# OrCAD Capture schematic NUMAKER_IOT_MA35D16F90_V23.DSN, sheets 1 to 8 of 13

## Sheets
1 00. System Block: size A; title: NuMaker-IoT-MA35D16F90 (LQFP216); rev: V2.3; company: nuvoTon Technology Corp.; note: 00. System Block
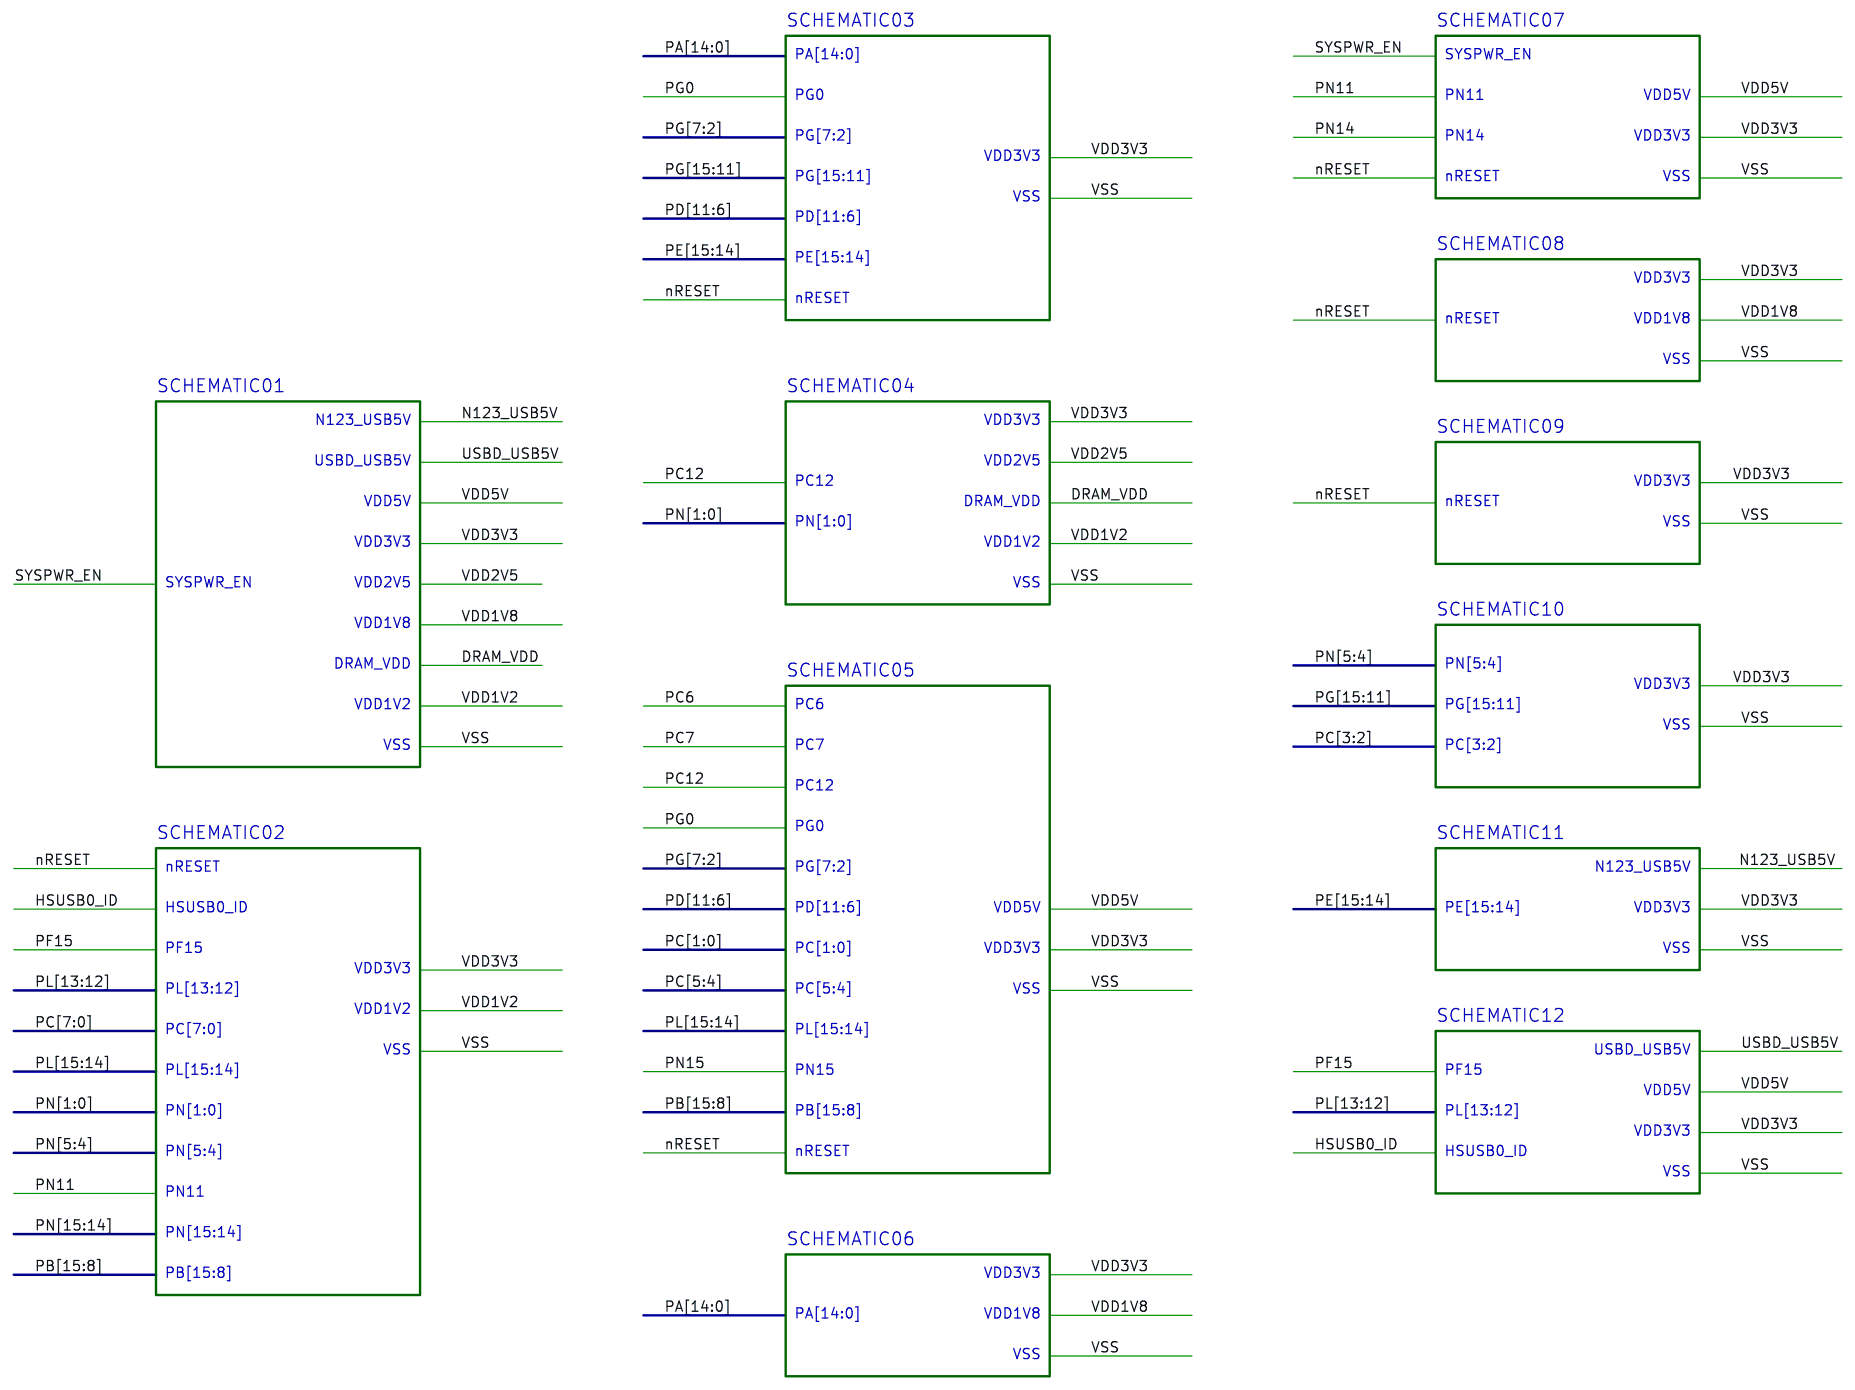
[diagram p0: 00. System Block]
2 08.RGMII0_RTL8211F(D)I (VDDIO8): size B; note: 08. RGMII0_RTL8211F(D)I (VDDIO8); block SCHEMATIC08
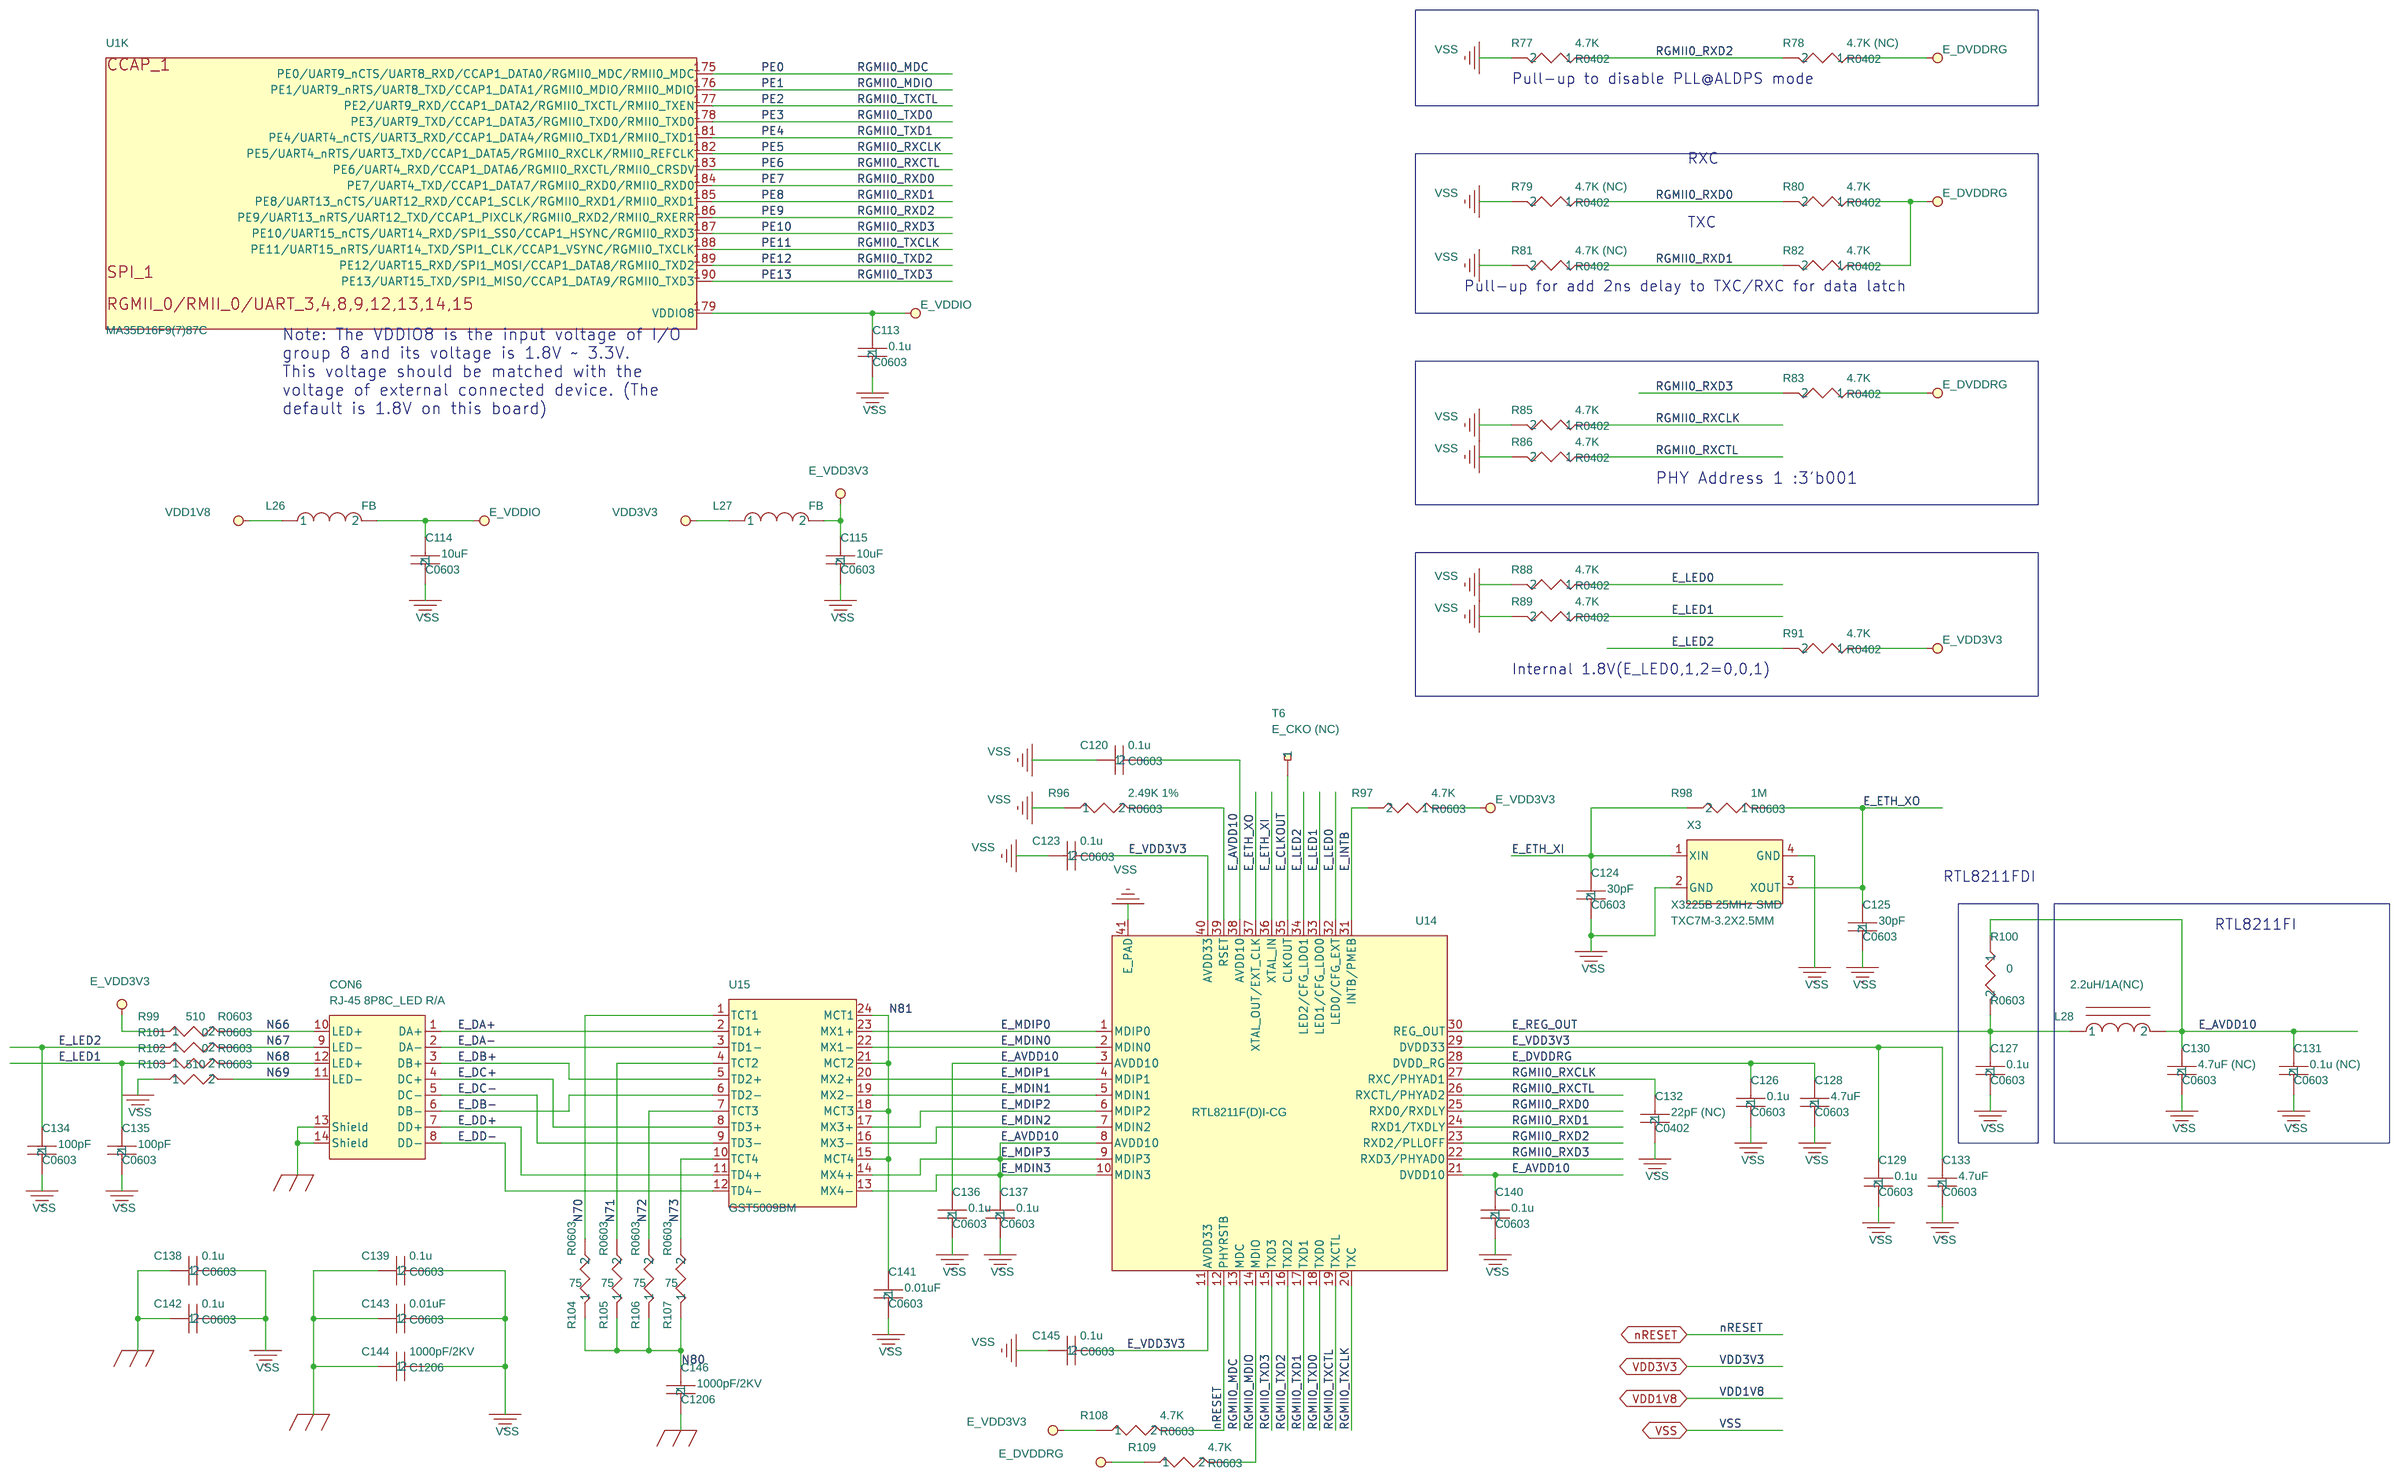
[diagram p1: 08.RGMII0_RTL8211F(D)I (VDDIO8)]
3 09. RMII1_RTL8201FI (VDDIO9): size B; note: 09. RMII1_RTL8201FI (VDDIO9); block SCHEMATIC09
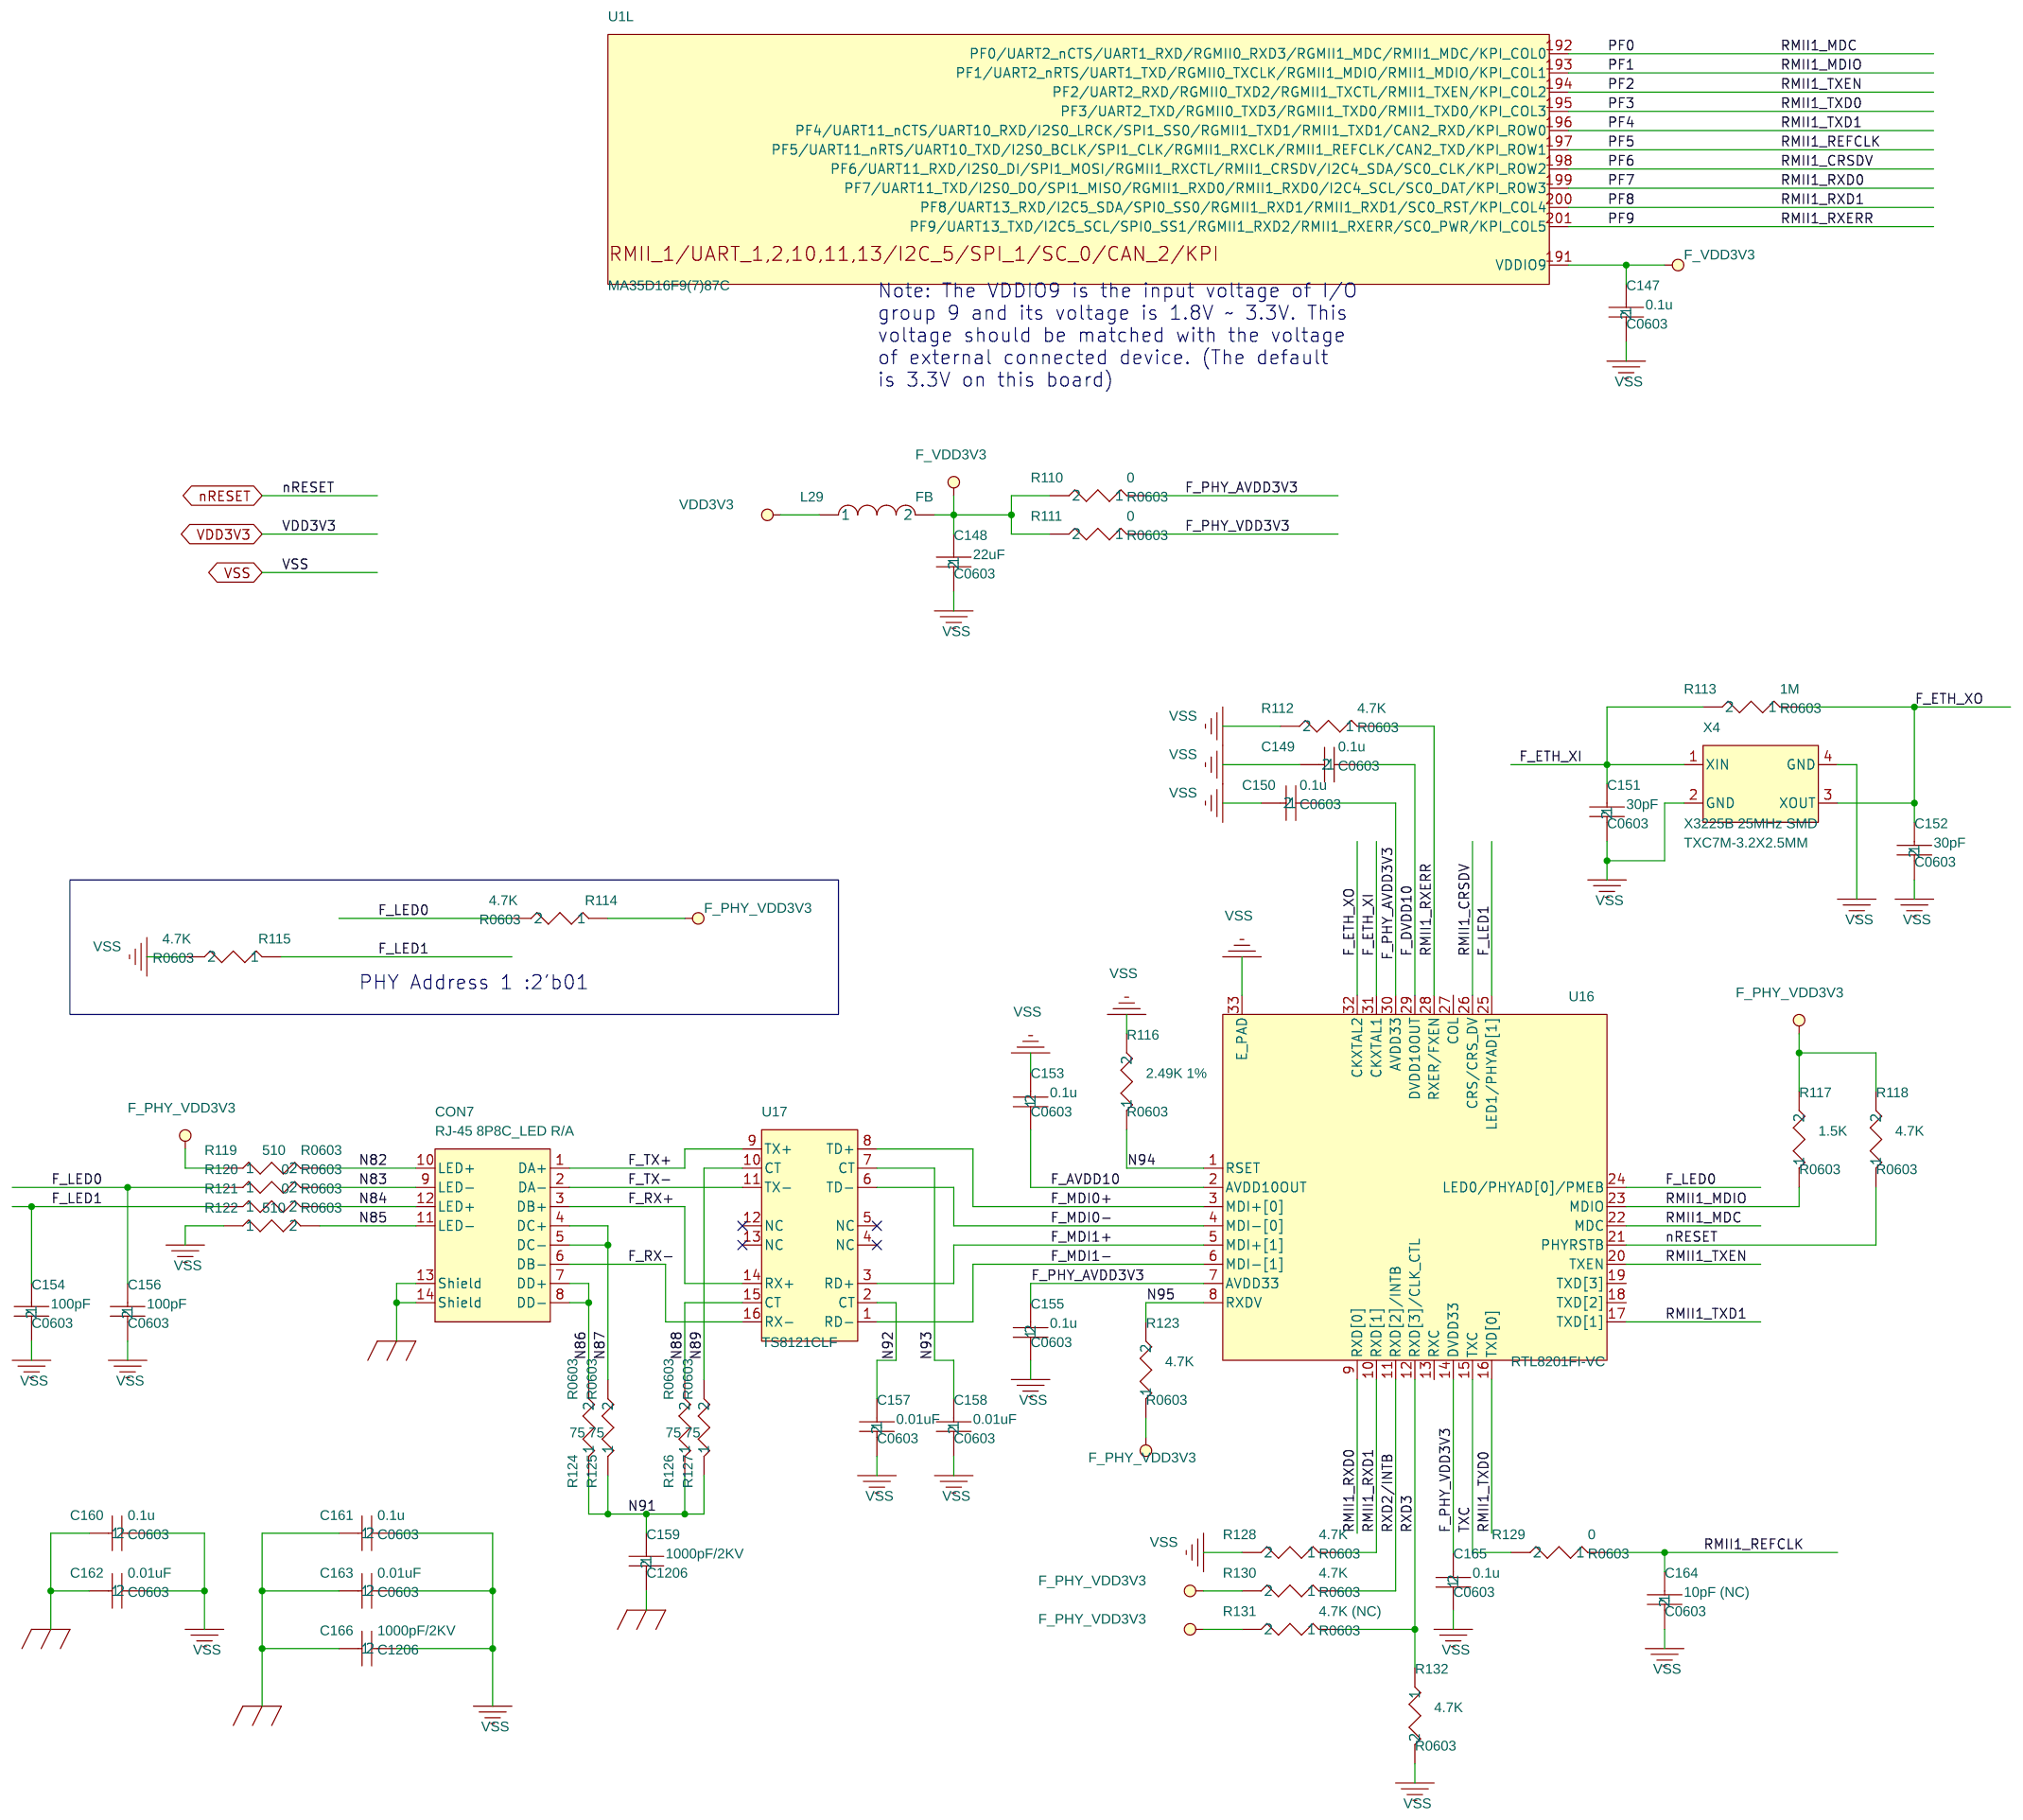
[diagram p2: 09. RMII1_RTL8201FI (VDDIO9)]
4 10. NAU88C22: size B; note: 10. NAU88C22; block SCHEMATIC10
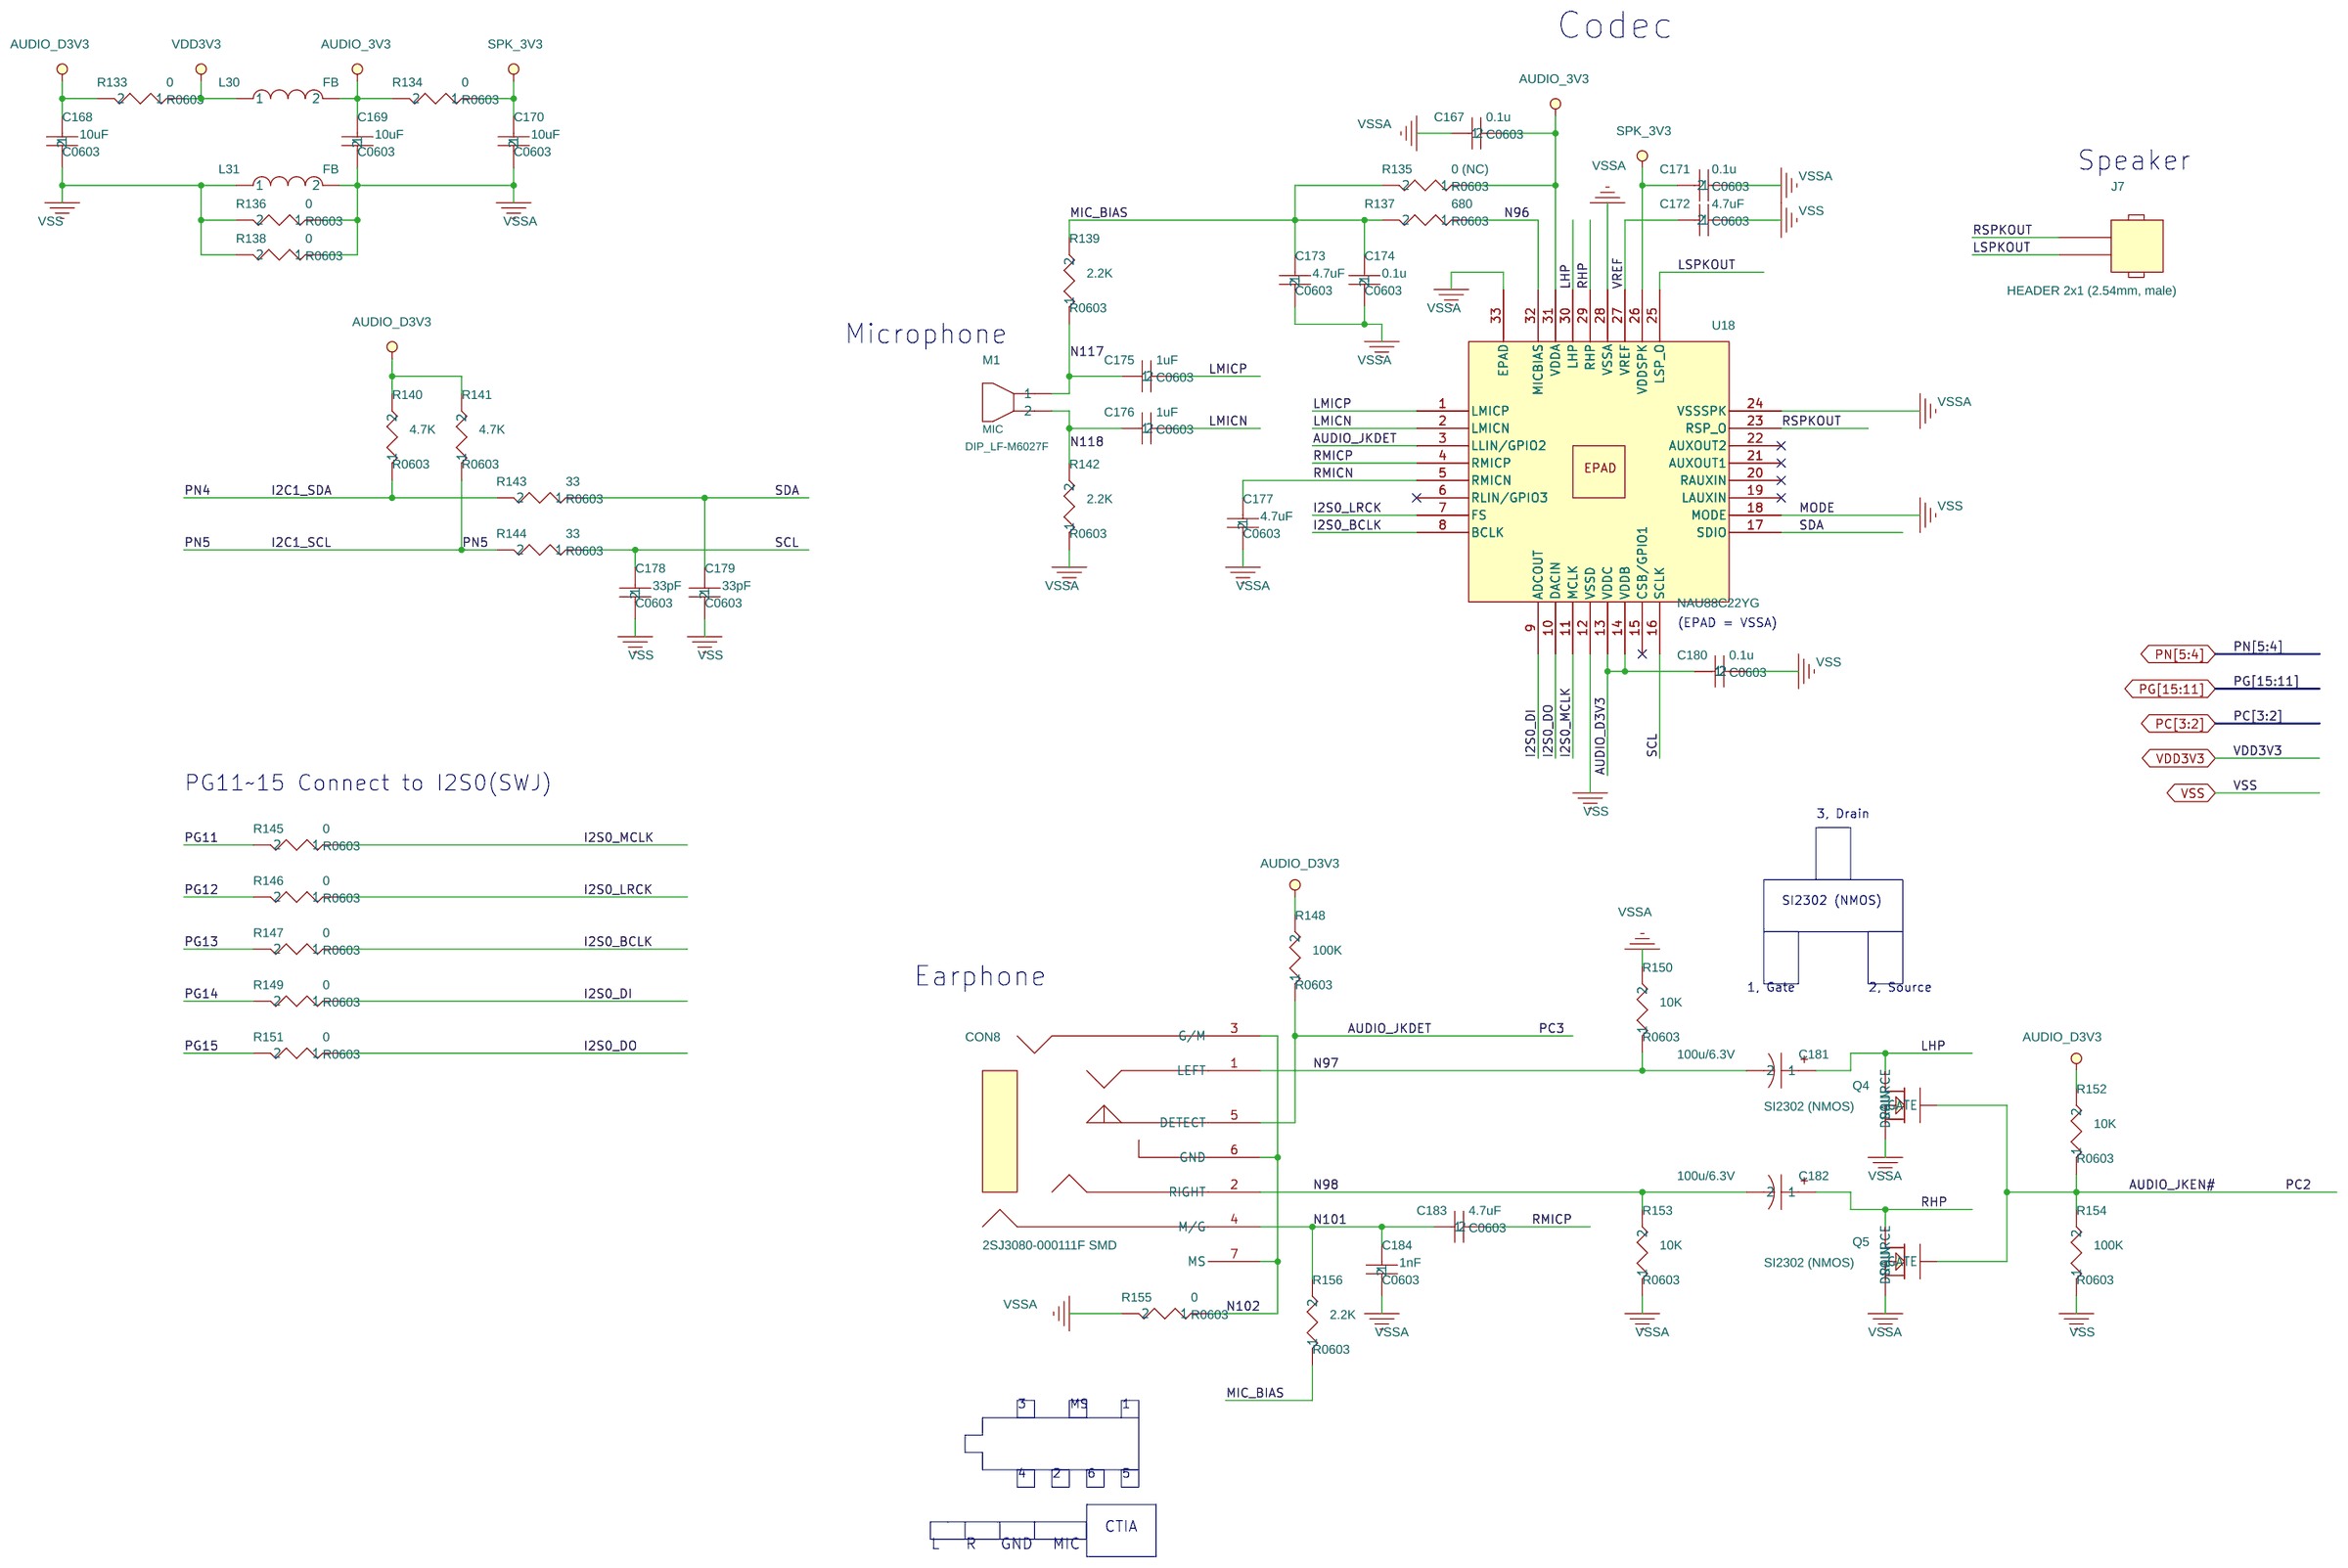
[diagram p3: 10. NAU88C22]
5 11. NUC123 VCOM: size B; note: 11. NUC123 VCOM; block SCHEMATIC11
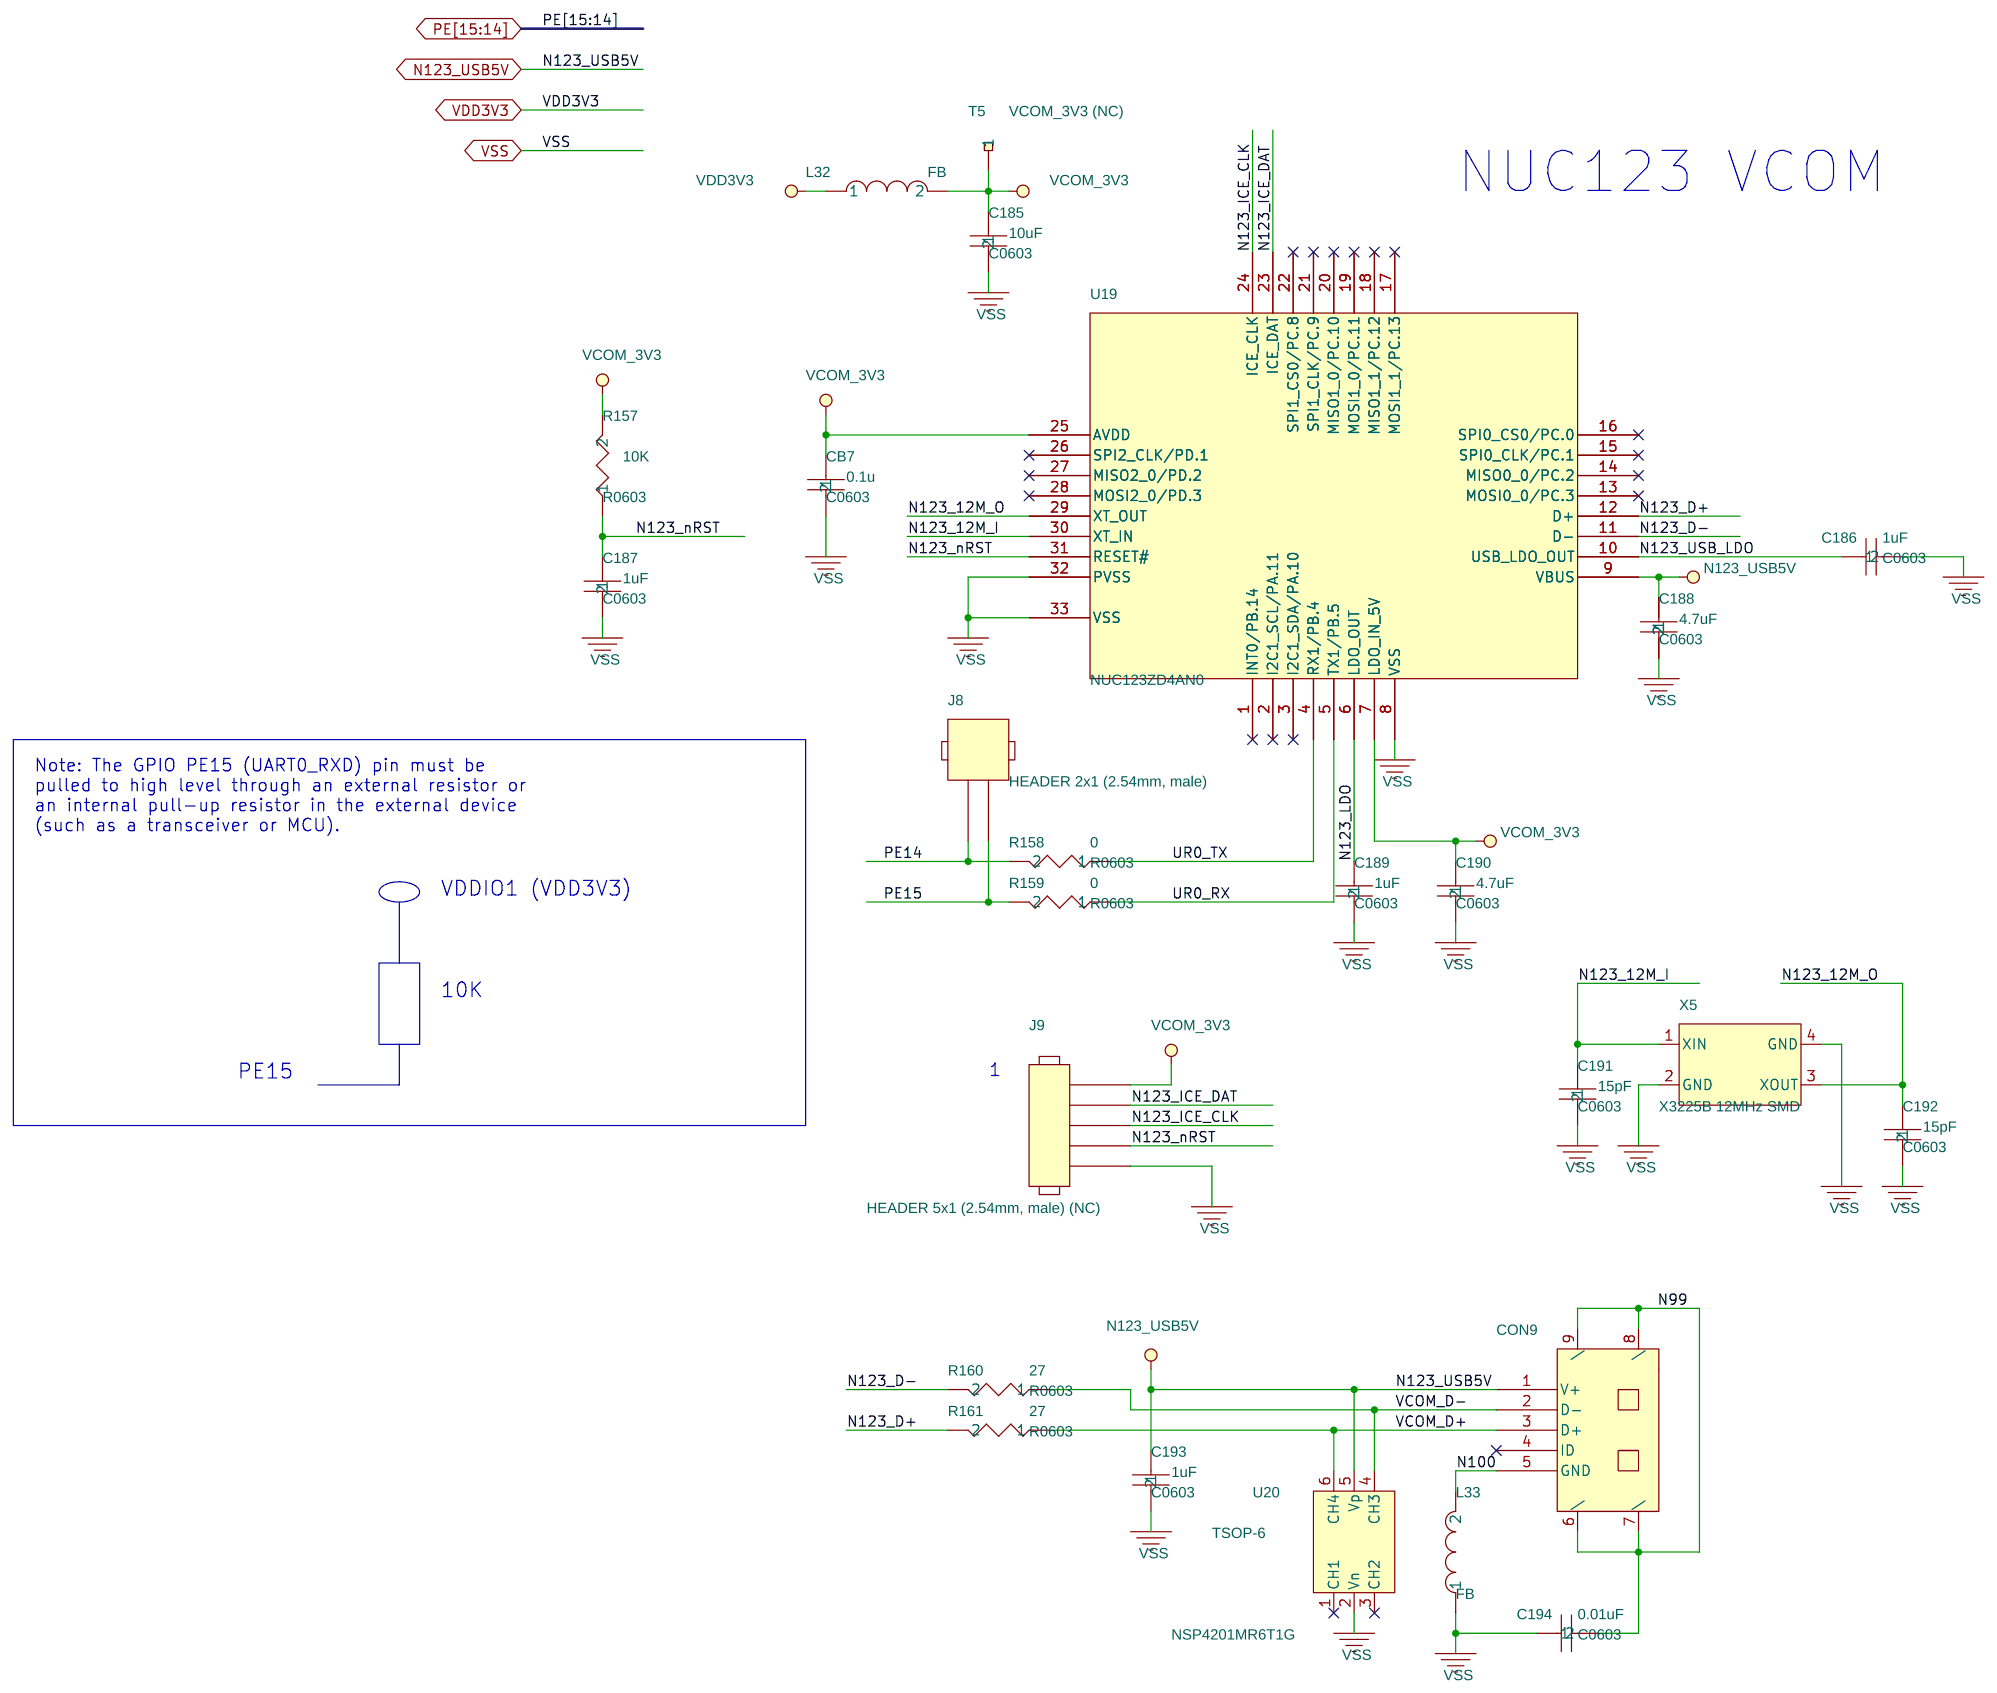
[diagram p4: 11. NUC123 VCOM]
6 12. High Speed USB: size B; note: 12. High Speed USB; block SCHEMATIC12
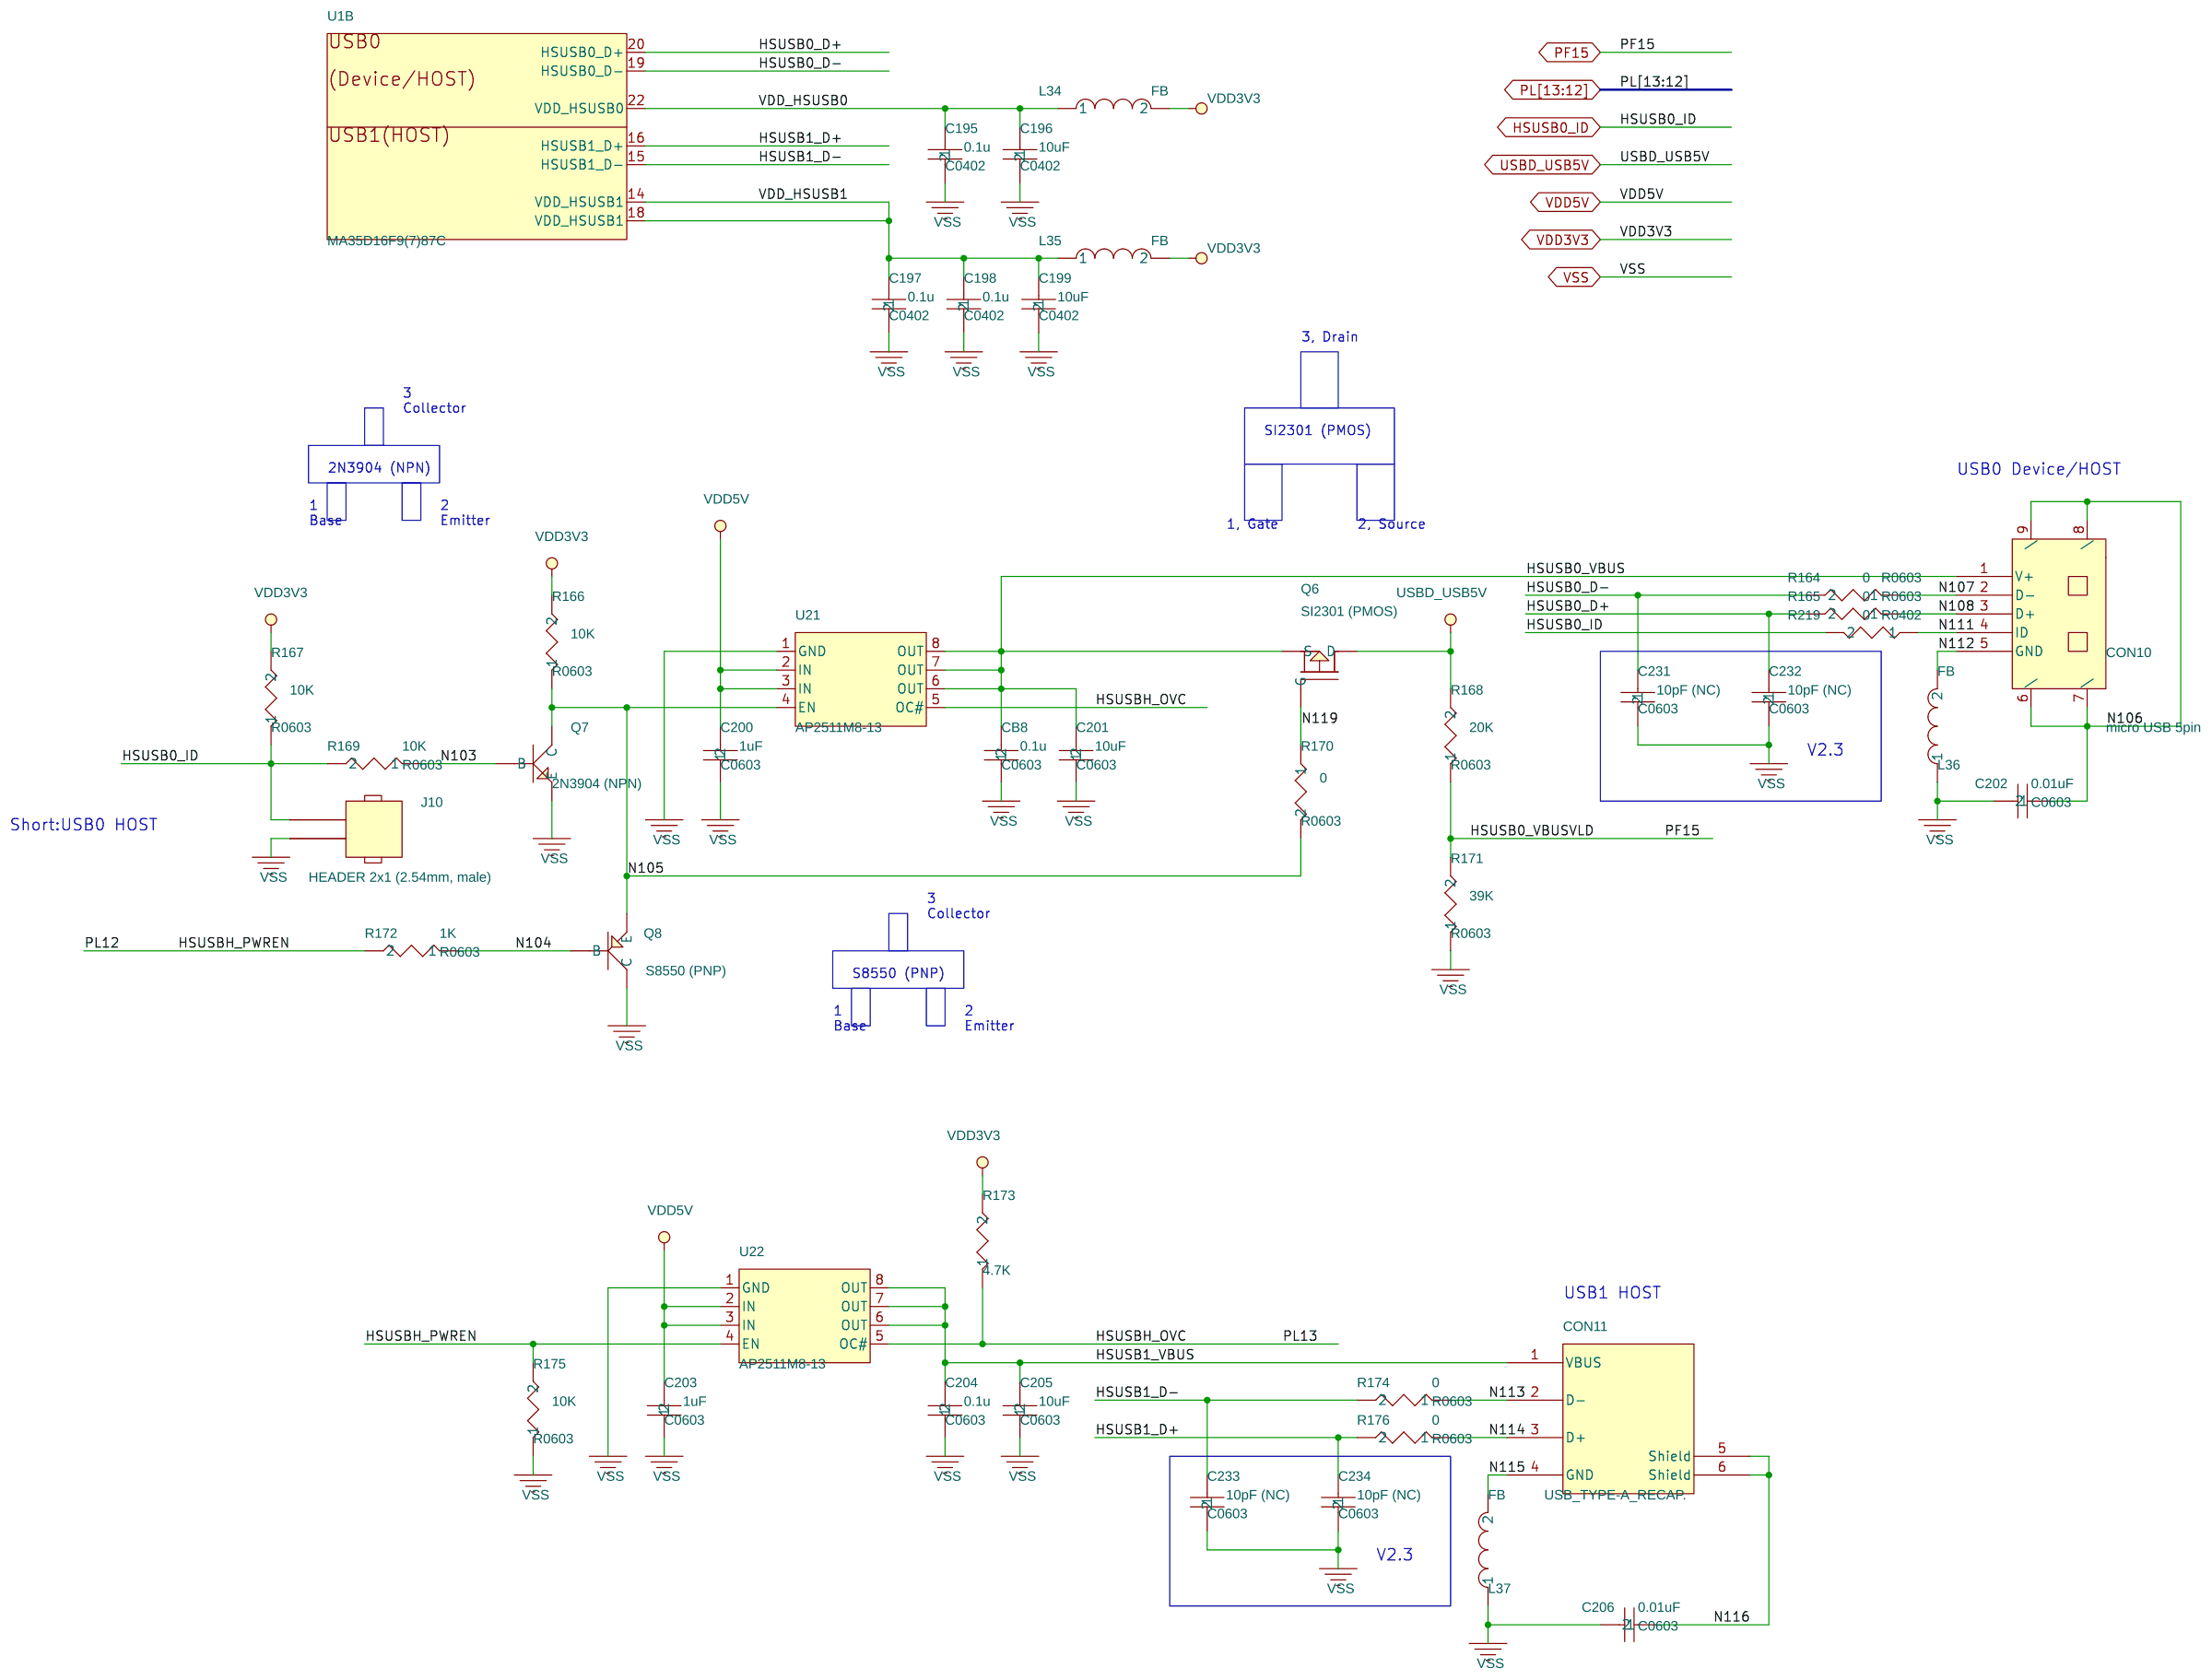
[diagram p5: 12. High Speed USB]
7 01. Power: size B; note: 01. Power; block SCHEMATIC01
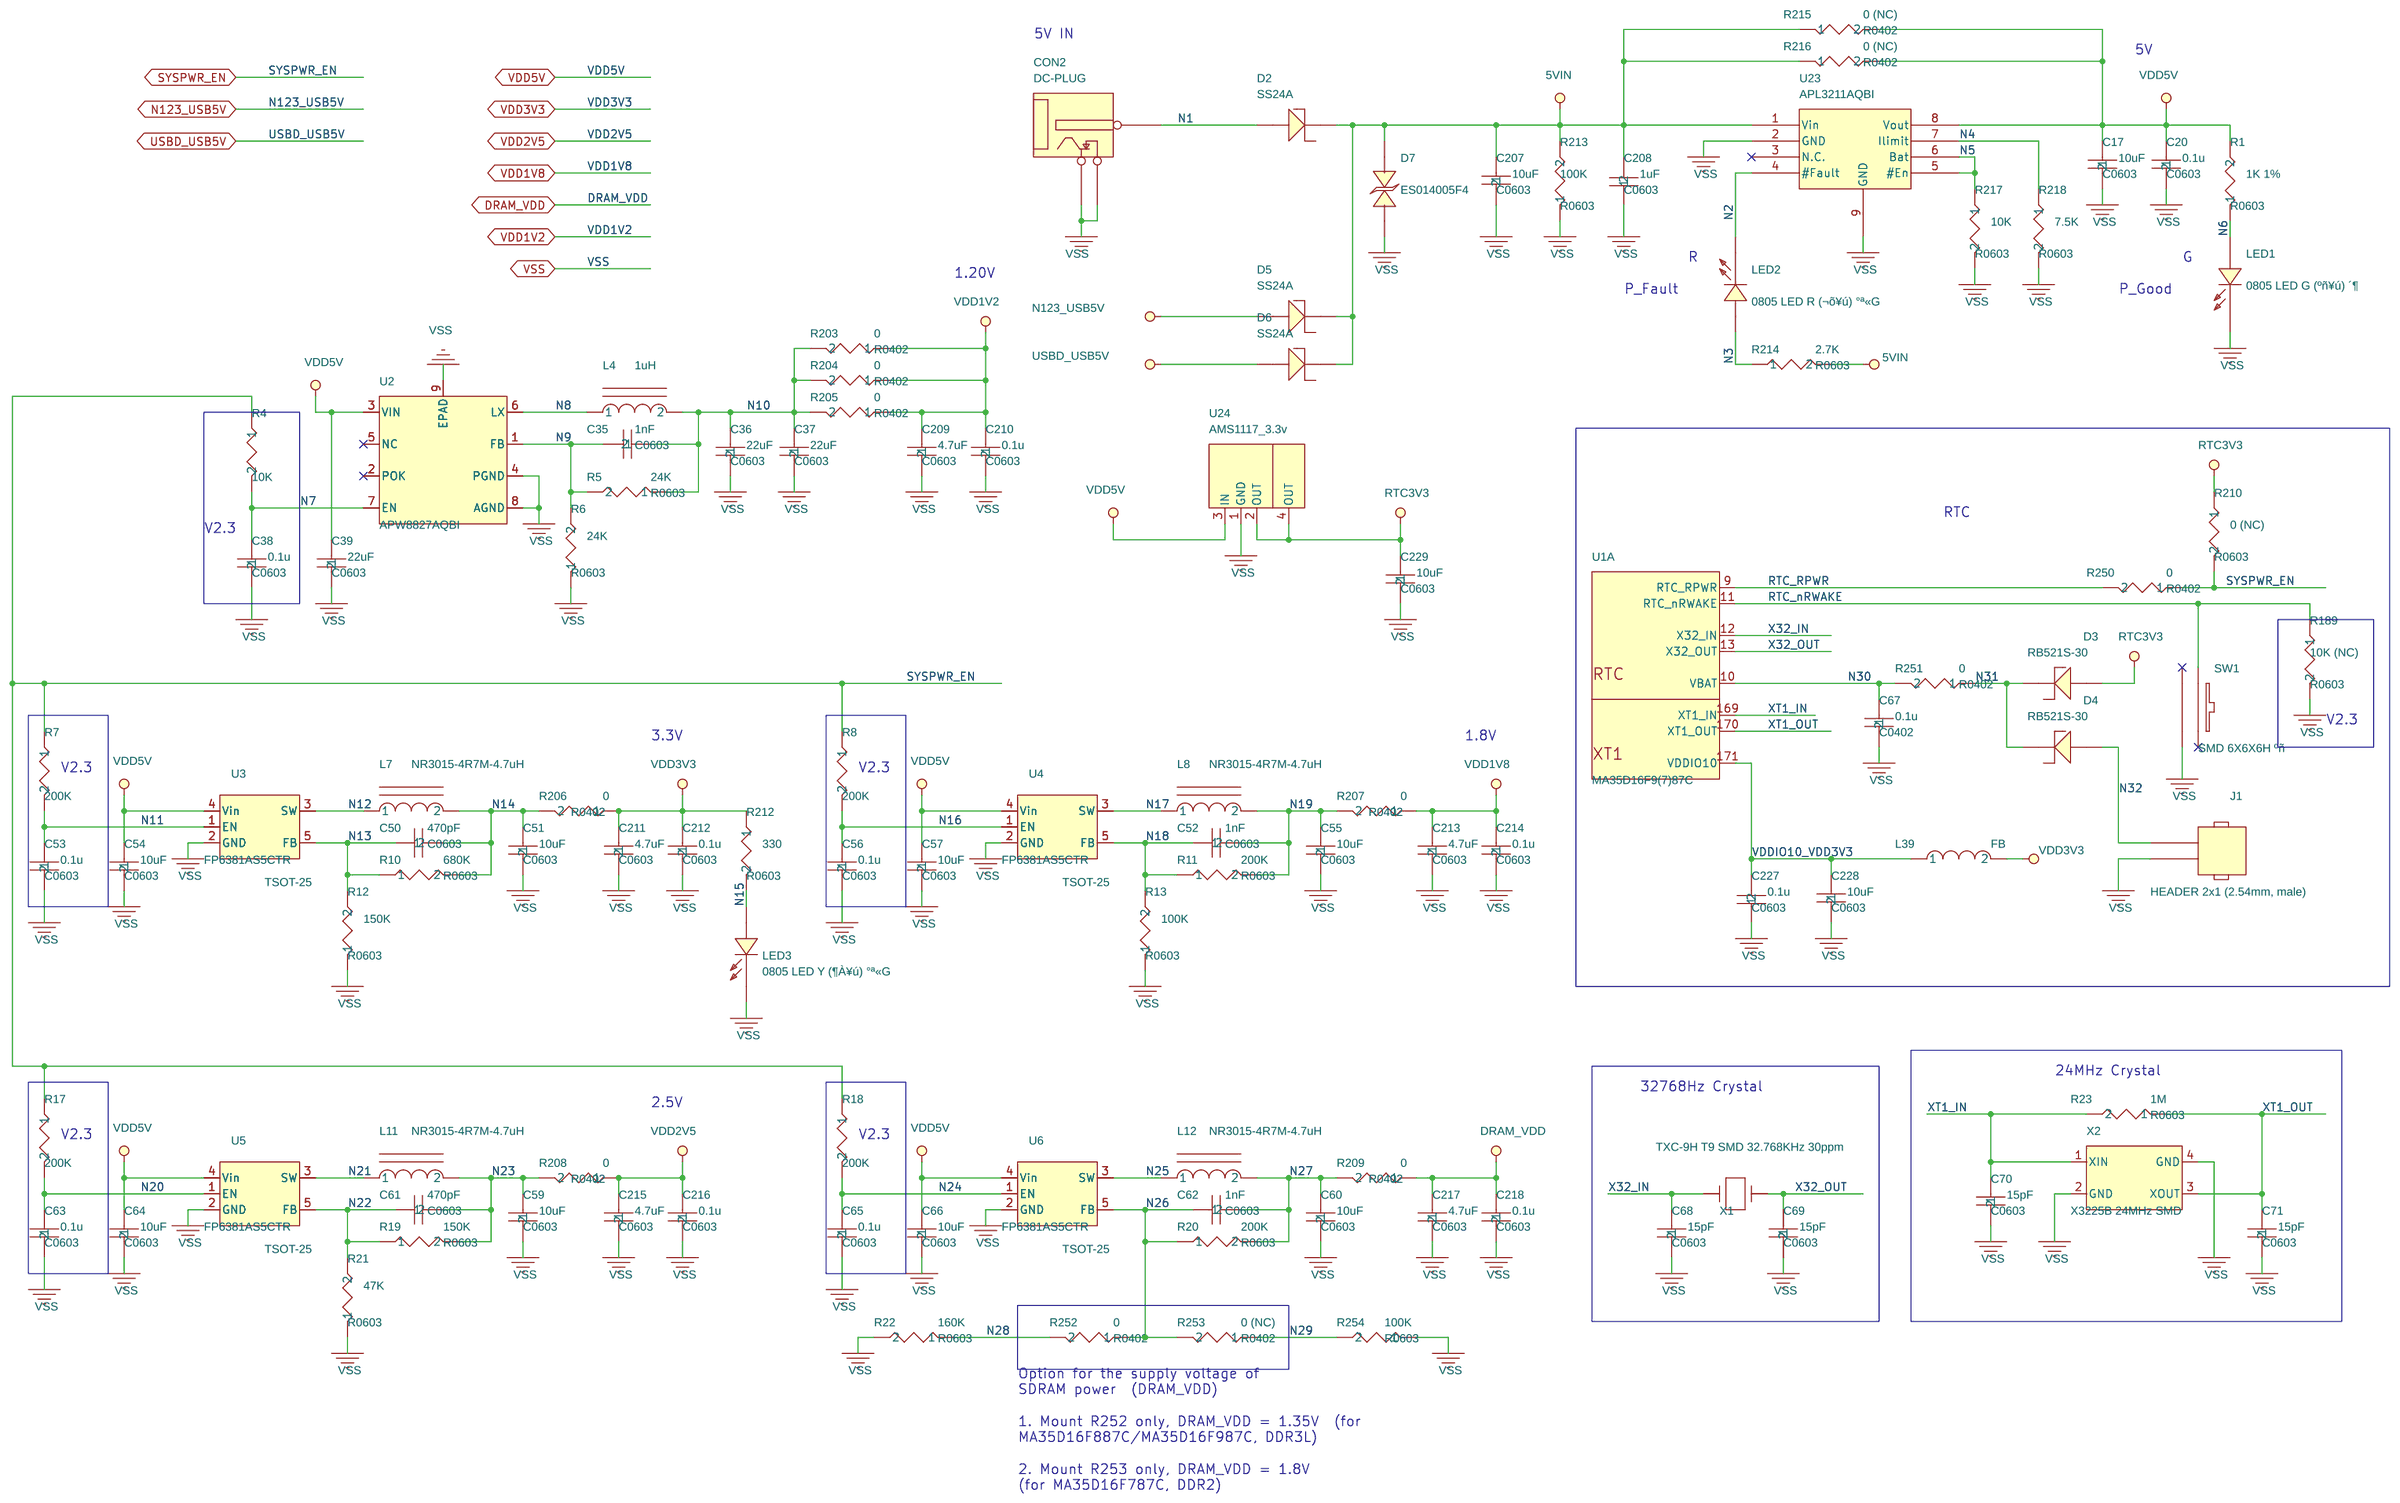
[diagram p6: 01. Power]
8 02. VDDIO0/6/7/ADC: size B; note: 02. VDDIO0/6/7/ADC; block SCHEMATIC02
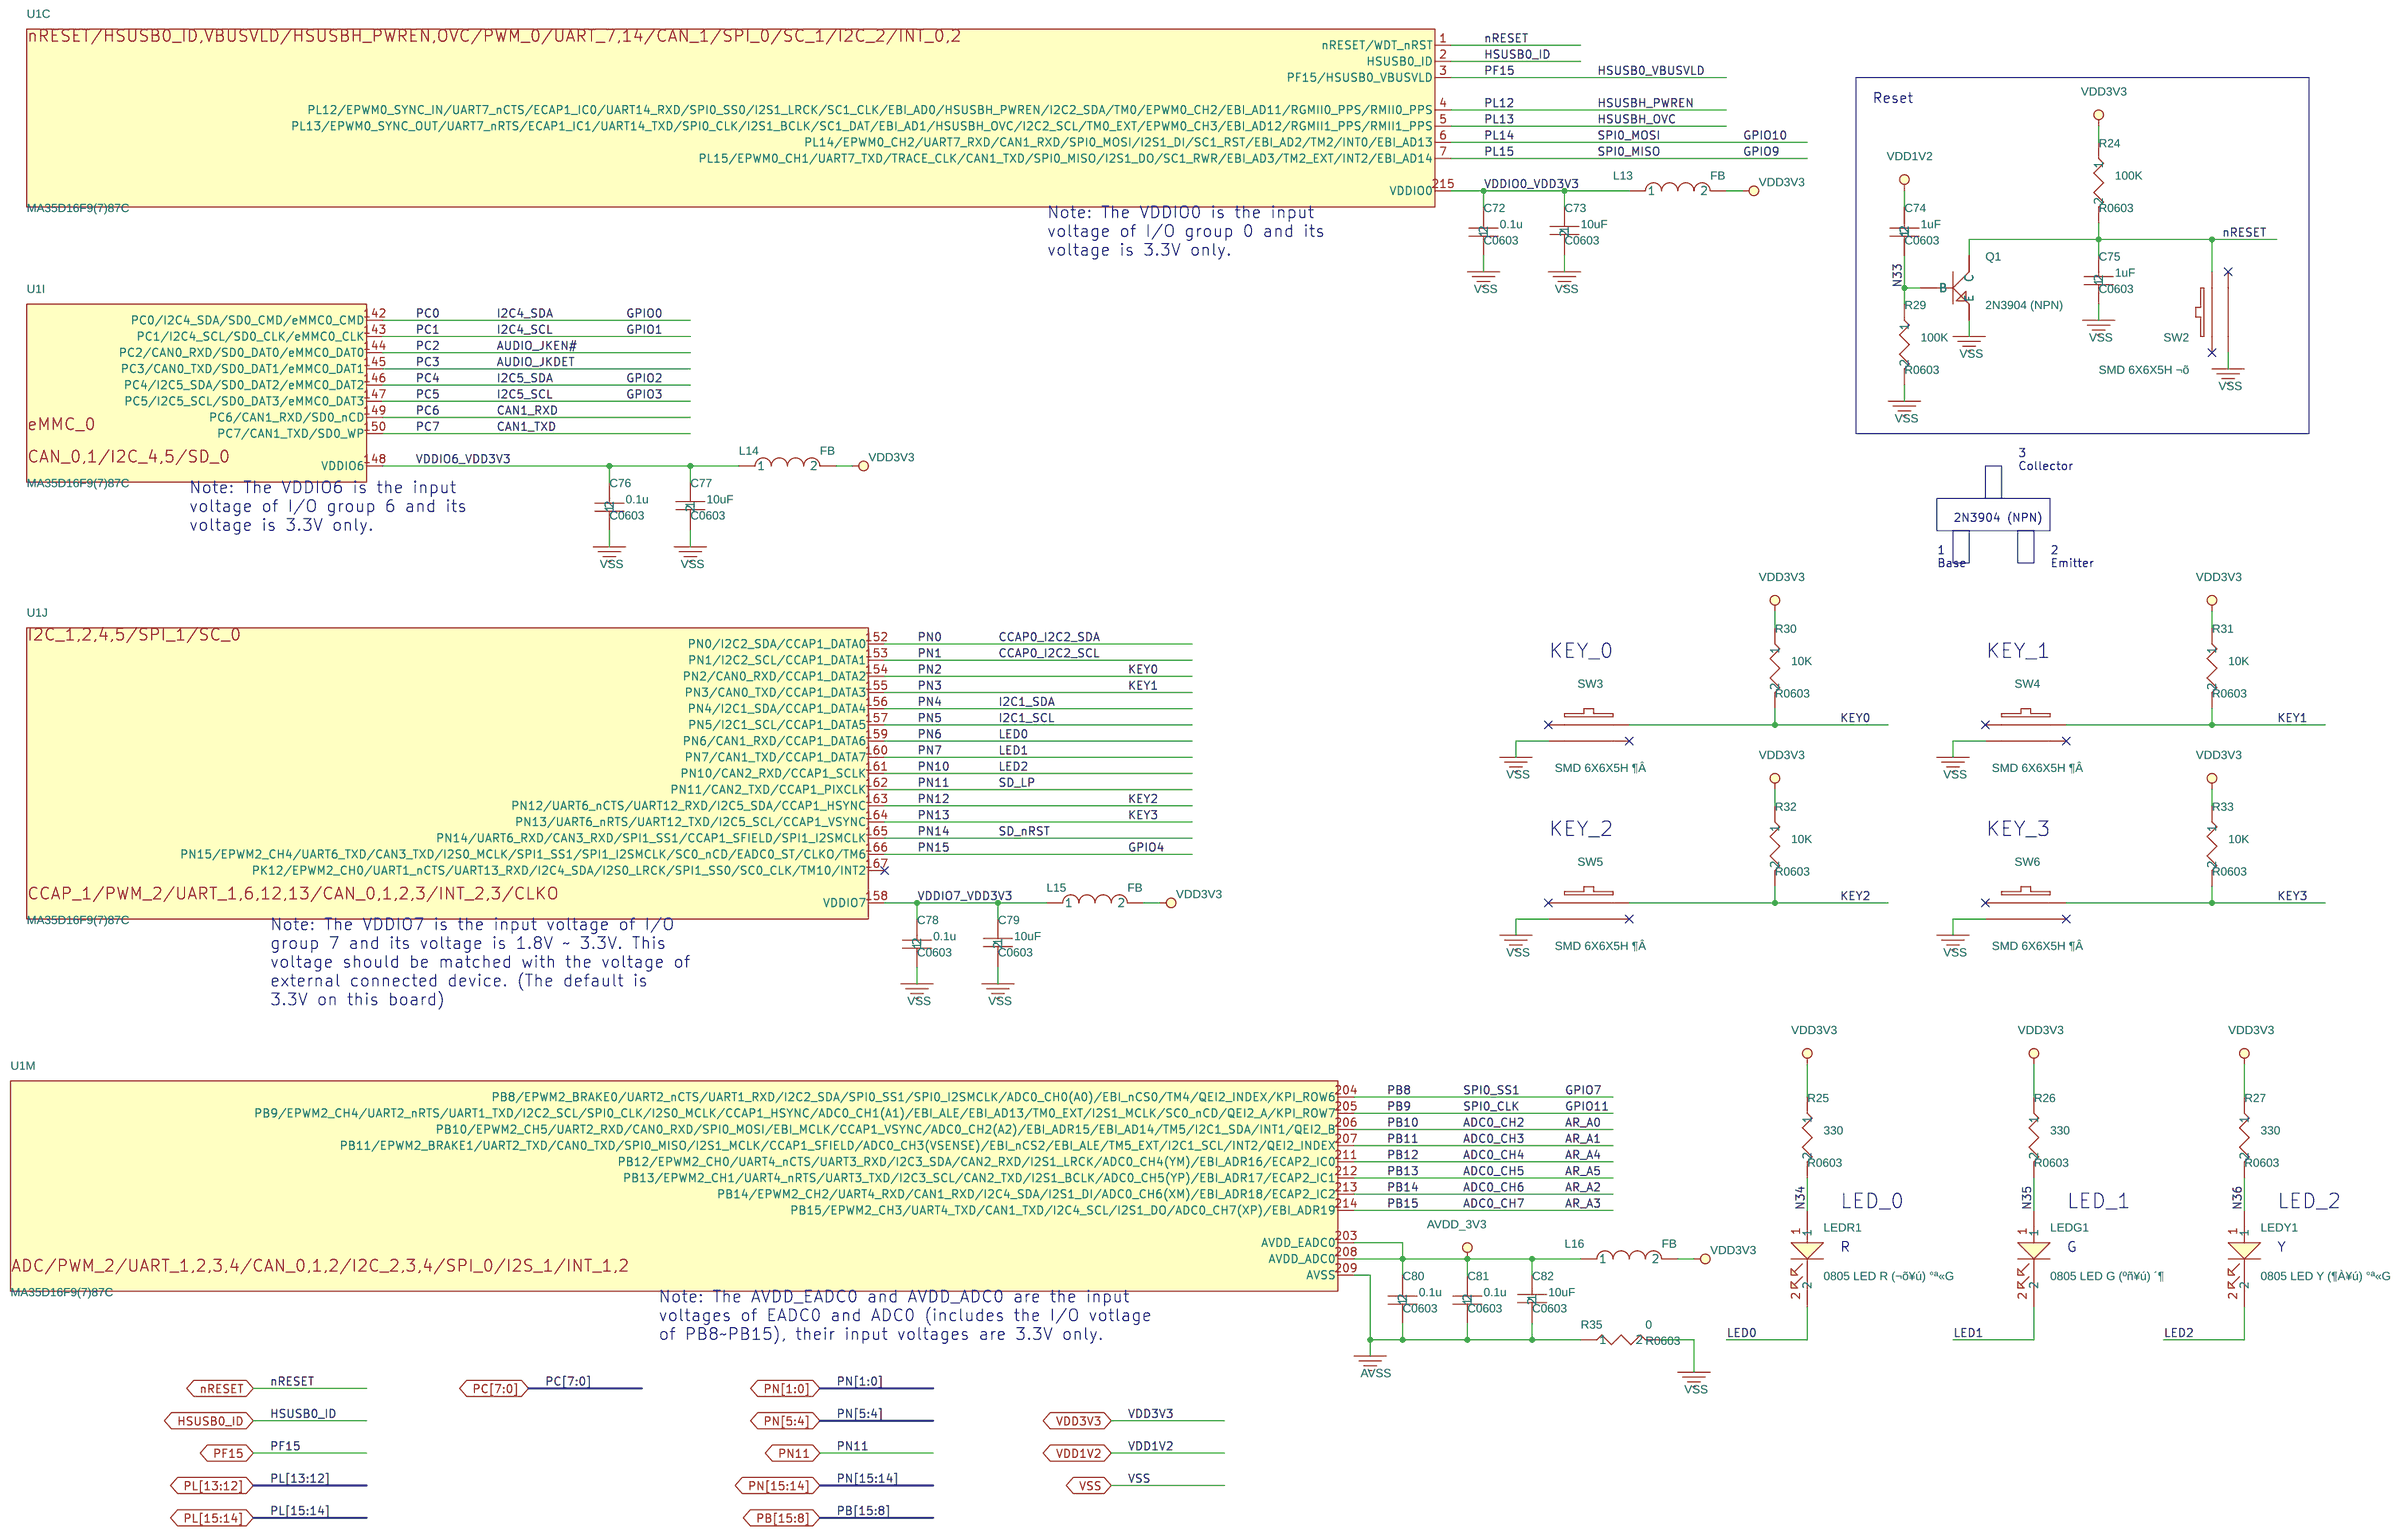
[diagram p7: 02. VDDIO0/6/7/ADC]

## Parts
sheet 01. Power
C17  10uF  [C0603]
C20  0.1u  [C0603]
C35  1nF  [C0603]
C36  22uF  [C0603]
C37  22uF  [C0603]
C38  0.1u  [C0603]
C39  22uF  [C0603]
C50  470pF  [C0603]
C51  10uF  [C0603]
C52  1nF  [C0603]
C53  0.1u  [C0603]
C54  10uF  [C0603]
C55  10uF  [C0603]
C56  0.1u  [C0603]
C57  10uF  [C0603]
C59  10uF  [C0603]
C60  10uF  [C0603]
C61  470pF  [C0603]
C62  1nF  [C0603]
C63  0.1u  [C0603]
C64  10uF  [C0603]
C65  0.1u  [C0603]
C66  10uF  [C0603]
C67  0.1u  [C0402]
C68  15pF  [C0603]
C69  15pF  [C0603]
C70  15pF  [C0603]
C71  15pF  [C0603]
C207  10uF  [C0603]
C208  1uF  [C0603]
C209  4.7uF  [C0603]
C210  0.1u  [C0603]
C211  4.7uF  [C0603]
C212  0.1u  [C0603]
C213  4.7uF  [C0603]
C214  0.1u  [C0603]
C215  4.7uF  [C0603]
C216  0.1u  [C0603]
C217  4.7uF  [C0603]
C218  0.1u  [C0603]
C227  0.1u  [C0603]
C228  10uF  [C0603]
C229  10uF  [C0603]
CON2  DC-PLUG  [POWRJACK\3P]
D2  SS24A  [DO-214AC]
D3  RB521S-30  [SOD-523]
D4  RB521S-30  [SOD-523]
D5  SS24A  [DO-214AC]
D6  SS24A  [DO-214AC]
D7  ES014005F4  [DFN1006]
J1  HEADER 2x1 (2.54mm, male)  [HEADER2x1]
L4  1uH  [SMTDR43]
L7  NR3015-4R7M-4.7uH  [SMTDR43]
L8  NR3015-4R7M-4.7uH  [SMTDR43]
L11  NR3015-4R7M-4.7uH  [SMTDR43]
L12  NR3015-4R7M-4.7uH  [SMTDR43]
L39  FB  [L0603]
LED1  0805 LED G (ºñ¥ú) ´¶  [LED0805]
LED2  0805 LED R (¬õ¥ú) °ª«G  [LED0805]
LED3  0805 LED Y (¶À¥ú) °ª«G  [LED_0805]
R1  1K 1%  [R0603]
R4  10K  [R0603]
R5  24K  [R0603]
R6  24K  [R0603]
R7  200K  [R0603]
R8  200K  [R0603]
R10  680K  [R0603]
R11  200K  [R0603]
R12  150K  [R0603]
R13  100K  [R0603]
R17  200K  [R0603]
R18  200K  [R0603]
R19  150K  [R0603]
R20  200K  [R0603]
R21  47K  [R0603]
R22  160K  [R0603]
R23  1M  [R0603]
R189  10K (NC)  [R0603]
R203  0  [R0402]
R204  0  [R0402]
R205  0  [R0402]
R206  0  [R0402]
R207  0  [R0402]
R208  0  [R0402]
R209  0  [R0402]
R210  0 (NC)  [R0603]
R212  330  [R0603]
R213  100K  [R0603]
R214  2.7K  [R0603]
R215  0 (NC)  [R0402]
R216  0 (NC)  [R0402]
R217  10K  [R0603]
R218  7.5K  [R0603]
R250  0  [R0402]
R251  0  [R0402]
R252  0  [R0402]
R253  0 (NC)  [R0402]
R254  100K  [R0603]
SW1  SMD 6X6X6H ºñ  [STS-B5]
U2  APW8827AQBI  [TDFN2x2-8]
U3  FP6381AS5CTR  [TSOT-25]
U4  FP6381AS5CTR  [TSOT-25]
U5  FP6381AS5CTR  [TSOT-25]
U6  FP6381AS5CTR  [TSOT-25]
U23  APL3211AQBI  [TDFN2x2-8]
U24  AMS1117_3.3v  [SOT-223-1]
X1  TXC-9H T9 SMD 32.768KHz 30ppm  [XTAL_2P/1.5mm]
X2  X3225B 24MHz SMD  [TXC7m-3.2x2.5mm]
sheet 02. VDDIO0/6/7/ADC
C72  0.1u  [C0603]
C73  10uF  [C0603]
C74  1uF  [C0603]
C75  1uF  [C0603]
C76  0.1u  [C0603]
C77  10uF  [C0603]
C78  0.1u  [C0603]
C79  10uF  [C0603]
C80  0.1u  [C0603]
C81  0.1u  [C0603]
C82  10uF  [C0603]
L13  FB  [L0603]
L14  FB  [L0603]
L15  FB  [L0603]
L16  FB  [L0603]
LEDG1  0805 LED G (ºñ¥ú) ´¶  [LED0805]
LEDR1  0805 LED R (¬õ¥ú) °ª«G  [LED0805]
LEDY1  0805 LED Y (¶À¥ú) °ª«G  [LED0805]
Q1  2N3904 (NPN)  [SOT-23]
R24  100K  [R0603]
R25  330  [R0603]
R26  330  [R0603]
R27  330  [R0603]
R29  100K  [R0603]
R30  10K  [R0603]
R31  10K  [R0603]
R32  10K  [R0603]
R33  10K  [R0603]
R35  0  [R0603]
SW2  SMD 6X6X5H ¬õ  [STS-B5]
SW3  SMD 6X6X5H ¶Â  [STS-B5]
SW4  SMD 6X6X5H ¶Â  [STS-B5]
SW5  SMD 6X6X5H ¶Â  [STS-B5]
SW6  SMD 6X6X5H ¶Â  [STS-B5]
sheet 08.RGMII0_RTL8211F(D)I (VDDIO8)
C113  0.1u  [C0603]
C114  10uF  [C0603]
C115  10uF  [C0603]
C120  0.1u  [C0603]
C123  0.1u  [C0603]
C124  30pF  [C0603]
C125  30pF  [C0603]
C126  0.1u  [C0603]
C127  0.1u  [C0603]
C128  4.7uF  [C0603]
C129  0.1u  [C0603]
C130  4.7uF (NC)  [C0603]
C131  0.1u (NC)  [C0603]
C132  22pF (NC)  [C0402]
C133  4.7uF  [C0603]
C134  100pF  [C0603]
C135  100pF  [C0603]
C136  0.1u  [C0603]
C137  0.1u  [C0603]
C138  0.1u  [C0603]
C139  0.1u  [C0603]
C140  0.1u  [C0603]
C141  0.01uF  [C0603]
C142  0.1u  [C0603]
C143  0.01uF  [C0603]
C144  1000pF/2KV  [C1206]
C145  0.1u  [C0603]
C146  1000pF/2KV  [C1206]
CON6  RJ-45 8P8C_LED R/A  [RJ45\8P\JA\LED]
L26  FB  [L0603]
L27  FB  [L0603]
L28  2.2uH/1A(NC)  [SMTDR43]
R77  4.7K  [R0402]
R78  4.7K (NC)  [R0402]
R79  4.7K (NC)  [R0402]
R80  4.7K  [R0402]
R81  4.7K (NC)  [R0402]
R82  4.7K  [R0402]
R83  4.7K  [R0402]
R85  4.7K  [R0402]
R86  4.7K  [R0402]
R88  4.7K  [R0402]
R89  4.7K  [R0402]
R91  4.7K  [R0402]
R96  2.49K 1%  [R0603]
R97  4.7K  [R0603]
R98  1M  [R0603]
R99  510  [R0603]
R100  0  [R0603]
R101  0  [R0603]
R102  0  [R0603]
R103  510  [R0603]
R104  75  [R0603]
R105  75  [R0603]
R106  75  [R0603]
R107  75  [R0603]
R108  4.7K  [R0603]
R109  4.7K  [R0603]
T6  E_CKO (NC)  [1PAD_1.25x1.25mm]
U1  MA35D16F9(7)87C  [LQFP216]  (sections A,B,C,D,E,F,G,H,I,J,K,L,M,N,O)
U14  RTL8211F(D)I-CG  [QFN40_0_4]
U15  GST5009BM  [GST5009BM]
X3  X3225B 25MHz SMD  [TXC7M-3.2X2.5MM]
sheet 09. RMII1_RTL8201FI (VDDIO9)
C147  0.1u  [C0603]
C148  22uF  [C0603]
C149  0.1u  [C0603]
C150  0.1u  [C0603]
C151  30pF  [C0603]
C152  30pF  [C0603]
C153  0.1u  [C0603]
C154  100pF  [C0603]
C155  0.1u  [C0603]
C156  100pF  [C0603]
C157  0.01uF  [C0603]
C158  0.01uF  [C0603]
C159  1000pF/2KV  [C1206]
C160  0.1u  [C0603]
C161  0.1u  [C0603]
C162  0.01uF  [C0603]
C163  0.01uF  [C0603]
C164  10pF (NC)  [C0603]
C165  0.1u  [C0603]
C166  1000pF/2KV  [C1206]
CON7  RJ-45 8P8C_LED R/A  [RJ45\8P\JA\LED]
L29  FB  [L0603]
R110  0  [R0603]
R111  0  [R0603]
R112  4.7K  [R0603]
R113  1M  [R0603]
R114  4.7K  [R0603]
R115  4.7K  [R0603]
R116  2.49K 1%  [R0603]
R117  1.5K  [R0603]
R118  4.7K  [R0603]
R119  510  [R0603]
R120  0  [R0603]
R121  0  [R0603]
R122  510  [R0603]
R123  4.7K  [R0603]
R124  75  [R0603]
R125  75  [R0603]
R126  75  [R0603]
R127  75  [R0603]
R128  4.7K  [R0603]
R129  0  [R0603]
R130  4.7K  [R0603]
R131  4.7K (NC)  [R0603]
R132  4.7K  [R0603]
U16  RTL8201FI-VC  [32-Pin QFN]
U17  TS8121CLF  [ST6200T]
X4  X3225B 25MHz SMD  [TXC7M-3.2X2.5MM]
sheet 10. NAU88C22
C167  0.1u  [C0603]
C168  10uF  [C0603]
C169  10uF  [C0603]
C170  10uF  [C0603]
C171  0.1u  [C0603]
C172  4.7uF  [C0603]
C173  4.7uF  [C0603]
C174  0.1u  [C0603]
C175  1uF  [C0603]
C176  1uF  [C0603]
C177  4.7uF  [C0603]
C178  33pF  [C0603]
C179  33pF  [C0603]
C180  0.1u  [C0603]
C181  100u/6.3V  [CAP_A]
C182  100u/6.3V  [CAP_A]
C183  4.7uF  [C0603]
C184  1nF  [C0603]
CON8  2SJ3080-000111F SMD  [PHONE-PJK-634M_AS]
J7  HEADER 2x1 (2.54mm, male)  [HEADER2x1]
L30  FB  [L0603]
L31  FB  [L0603]
M1  MIC  [DIP_LF-M6027F]
Q4  SI2302 (NMOS)  [SOT-23]
Q5  SI2302 (NMOS)  [SOT-23]
R133  0  [R0603]
R134  0  [R0603]
R135  0 (NC)  [R0603]
R136  0  [R0603]
R137  680  [R0603]
R138  0  [R0603]
R139  2.2K  [R0603]
R140  4.7K  [R0603]
R141  4.7K  [R0603]
R142  2.2K  [R0603]
R143  33  [R0603]
R144  33  [R0603]
R145  0  [R0603]
R146  0  [R0603]
R147  0  [R0603]
R148  100K  [R0603]
R149  0  [R0603]
R150  10K  [R0603]
R151  0  [R0603]
R152  10K  [R0603]
R153  10K  [R0603]
R154  100K  [R0603]
R155  0  [R0603]
R156  2.2K  [R0603]
U18  NAU88C22YG  [QFN32L_5x5mm\0.5mm_pitch]
sheet 11. NUC123 VCOM
C185  10uF  [C0603]
C186  1uF  [C0603]
C187  1uF  [C0603]
C188  4.7uF  [C0603]
C189  1uF  [C0603]
C190  4.7uF  [C0603]
C191  15pF  [C0603]
C192  15pF  [C0603]
C193  1uF  [C0603]
C194  0.01uF  [C0603]
CB7  0.1u  [C0603]
CON9  micro USB 5pin  [MICRO_USB_AB_LS]
J8  HEADER 2x1 (2.54mm, male)  [HEADER2x1]
J9  HEADER 5x1 (2.54mm, male) (NC)  [HEADER5x1]
L32  FB  [L0603]
L33  FB  [L0603]
R157  10K  [R0603]
R158  0  [R0603]
R159  0  [R0603]
R160  27  [R0603]
R161  27  [R0603]
T5  VCOM_3V3 (NC)  [1PAD_1.25x1.25mm]
U19  NUC123ZD4AN0  [QFN33_5X5]
U20  NSP4201MR6T1G  [TSOP-6]
X5  X3225B 12MHz SMD  [TXC7m-3.2x2.5mm]
sheet 12. High Speed USB
C195  0.1u  [C0402]
C196  10uF  [C0402]
C197  0.1u  [C0402]
C198  0.1u  [C0402]
C199  10uF  [C0402]
C200  1uF  [C0603]
C201  10uF  [C0603]
C202  0.01uF  [C0603]
C203  1uF  [C0603]
C204  0.1u  [C0603]
C205  10uF  [C0603]
C206  0.01uF  [C0603]
C231  10pF (NC)  [C0603]
C232  10pF (NC)  [C0603]
C233  10pF (NC)  [C0603]
C234  10pF (NC)  [C0603]
CB8  0.1u  [C0603]
CON10  micro USB 5pin  [MICRO_USB_AB_LS]
CON11  USB_TYPE-A_RECAP.  [USB4P]
J10  HEADER 2x1 (2.54mm, male)  [HEADER2x1]
L34  FB  [L0603]
L35  FB  [L0603]
L36  FB  [L0603]
L37  FB  [L0603]
Q6  SI2301 (PMOS)  [SOT-23]
Q7  2N3904 (NPN)  [SOT-23]
Q8  S8550 (PNP)  [SOT-23]
R164  0  [R0603]
R165  0  [R0603]
R166  10K  [R0603]
R167  10K  [R0603]
R168  20K  [R0603]
R169  10K  [R0603]
R170  0  [R0603]
R171  39K  [R0603]
R172  1K  [R0603]
R173  4.7K  [R0603]
R174  0  [R0603]
R175  10K  [R0603]
R176  0  [R0603]
R219  0  [R0402]
U21  AP2511M8-13  [MSOP-8]
U22  AP2511M8-13  [MSOP-8]

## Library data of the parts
C17 C77 C126 C158 C178 C190 C231 = CAP-C: Package: 0603
C20 C120 = CAP-C_26: Package: 0603
C35 = CAP-C_28: Package: 0603
C36 = CAP-C_39: Package: 0603
C37 = CAP-C_35: Package: 0603
C38 C123 = CAP-C_21: Package: 0603
C39 = CAP-C_41: Package: 0603
C50 = CAP-C_30: Package: 0603
C51 = CAP-C_40: Package: 0603
C52 C124 C154 = CAP-C_19: Package: 0603
C53 = CAP-C_34: Package: 0603
C54 C130 C148 C174 C196 = CAP-C_13: Package: 0603
C55 = CAP-C_29: Package: 0603
C56 C76 C139 C166 C183 C189 CB8 = CAP-C_5: Package: 0603
C57 = CAP-C_31: Package: 0603
C59 C129 C162 C201 = CAP-C_16: Package: 0603
C60 = CAP-C_42: Package: 0603
C61 C138 = CAP-C_23: Package: 0603
C62 C136 = CAP-C_20: Package: 0603
C63 C72 C160 C170 C192 C205 = CAP-C_2: Package: 0603
C64 C135 = CAP-C_24: Package: 0603
C65 C142 C147 = CAP-C_17: Package: 0603
C66 = CAP-C_38: Package: 0603
C67 = CAP-C_10: Package: 0402
C68 C131 C156 C172 C206 = CAP-C_11: Package: 0603
C69 C137 C157 C179 = CAP-C_15: Package: 0603
C70 C80 C144 C149 C168 C186 C204 = CAP-C_9: Package: 0603
C71 C74 C143 C163 C177 C187 = CAP-C_4: Package: 0603
C207 = CAP-C_33: Package: 0603
C79 C113 C153 C180 C191 C208 C232 = CAP-C_8: Package: 0603
C209 = CAP-C_32: Package: 0603
C128 C210 = CAP-C_22: Package: 0603
C115 C164 C171 C200 C211 = CAP-C_12: Package: 0603
C212 = CAP-C_36: Package: 0603
C213 = CAP-C_37: Package: 0603
C146 C151 C214 = CAP-C_18: Package: 0603
C78 C140 C150 C176 C185 C215 = CAP-C_1: Package: 0603
C127 C216 = CAP-C_27: Package: 0603
C141 C217 = CAP-C_25: Package: 0603
C82 C114 C155 C167 C194 C218 C234 = CAP-C_3: Package: 0603
C134 C161 C173 C203 C227 = CAP-C_14: Package: 0603
C75 C125 C165 C175 C199 C228 CB7 = CAP-C_6: Package: 0603
C81 C133 C159 C169 C188 C229 C233 = CAP-C_7: Package: 0603
CON2 = Power_Jack
D2-D6 = ZENAR_0: Package: D
D7 = DIODE_TAZ_BI-DIR
J1 J7 J8 J10 = HEADER_2
L4 = INDUCTOR_IRON_1
L7 = INDUCTOR_IRON_2
L8 = INDUCTOR_IRON_4
L11 = INDUCTOR_IRON_3
L12 L28 = INDUCTOR_IRON
L14 L26 L29 L30 L33 L35 L39 = INDUCTOR
LED1-LED3 = LED
R1 R26 R80 R132 R153 R171 = R_0_5: Package: 0603
R4 = R_2
R5 R102 R114 R141 = R_0_18: Package: 0603
R6 = R_0_31: Package: 0603
R7 R173 = R
R8 = R_4
R10 R24 R96 R126 R152 R160 R166 = R_0_2: Package: 0603
R11 R101 R125 R140 = R_0_21: Package: 0603
R12 R109 R131 R134 = R_0_20: Package: 0603
R13 R30 R83 R121 R142 R158 R174 = R_0: Package: 0603
R17 = R_1
R18 = R_3
R19 R86 R133 = R_0_23: Package: 0603
R20 R27 R81 R113 R138 R165 = R_0_7: Package: 0603
R21 R31 R107 R112 R154 R159 R169 = R_0_1: Package: 0603
R22 R97 R129 R147 = R_0_14: Package: 0603
R23 R91 R117 R136 R175 = R_0_11: Package: 0603
R99 R120 R143 R189 = R_0_22: Package: 0603
R100 R116 R156 R203 = R_0_16: Package: 0603
R33 R77 R119 R150 R168 R204 = R_0_9: Package: 0603
R79 R124 R135 R205 = R_0_13: Package: 0603
R206 = R_0_28: Package: 0603
R103 R110 R148 R176 R207 = R_0_12: Package: 0603
R208 = R_0_27: Package: 0603
R78 R115 R155 R209 = R_0_17: Package: 0603
R104 R122 R149 R164 R210 = R_0_10: Package: 0603
R212 = R_0_32: Package: 0603
R88 R123 R144 R213 = R_0_19: Package: 0603
R25 R105 R111 R137 R170 R214 = R_0_8: Package: 0603
R89 R127 R146 R215 = R_0_15: Package: 0603
R32 R106 R128 R139 R161 R167 R216 = R_0_4: Package: 0603
R217 = R_0_29: Package: 0603
R108 R218 = R_0_24: Package: 0603
R250 = R_0_26: Package: 0603
R251 = R_0_30: Package: 0603
R85 R252 = R_0_25: Package: 0603
R29 R82 R130 R145 R157 R172 R253 = R_0_3: Package: 0603
R35 R98 R118 R151 R219 R254 = R_0_6: Package: 0603
SW1 SW6 = SW-S
U2 = APW8827AQBI
U3-U6 = ZT7103S_0
U23 = APL3203A_1
U24 = TO-247_Regulator_10
X1 = MA306_SM_2: Vendor: TXC
X2 X5 = Crystal_SMD_2
C73 C145 C152 C184 C193 C202 = CAP-C_10: Package: 0603
L13 L27 L31 L32 L36 = INDUCTOR_1
L15 L37 = INDUCTOR_3
L16 L34 = INDUCTOR_2
LEDG1 = LED_0_1: Package: KP-2012; Vendor: Kingbright
LEDR1 = LED_0_2: Package: KP-2012; Vendor: Kingbright
LEDY1 = LED_0: Package: KP-2012; Vendor: Kingbright
Q1 Q7 = PNP_0
SW2 = SW-S_4
SW3 = SW-S_3
SW4 = SW-S_2
SW5 = SW-S_1
C132 = CAP-C_2: Package: 0402
CON6 CON7 = RJ45_SHLD_2
T5 T6 = 1PAD_1
U1 = MA35D1_LQFP216
U14 = RTL8211F(D)I-CG
U15 = GST5009BM
X3 X4 = Crystal_SMD_2: Vendor: Aurum
U16 = RTL8201FI-VC
U17 = PE-68515_2
C181 = CAP-T
C182 = CAP-T_1
CON8 = SJ-435107RS_9: Part Number: CP-435107RS-ND; Vendor: Digikey
M1 = MICROPHONE_2
Q4 Q5 = MOSFET_N_4
U18 = NAU8501_0
CON9 CON10 = USB_Type_B_0
J9 = HEADER_5
U19 = NUC101_QFN_0
U20 = PJ9293_0
C195 = CAP-C_4: Package: 0402
C197 = CAP-C_1: Package: 0402
C198 = CAP-C_15: Package: 0402
CON11 = USB_type_A_connector
Q6 = MOSFET_P_4
Q8 = PNP_2
U21 = NCT3520W-H15_0
U22 = NCT3520W-H15_1

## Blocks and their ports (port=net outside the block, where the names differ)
SCHEMATIC11 = schematic 11. SCHEMATIC, on sheet 00. System Block: VSS, PE[15:14], VDD3V3, N123_USB5V
SCHEMATIC12 = schematic 12. SCHEMATIC, on sheet 00. System Block: VSS, PL[13:12], PF15, HSUSB0_ID, VDD5V, VDD3V3, USBD_USB5V
SCHEMATIC06 = schematic 06. SCHEMATIC, on sheet 00. System Block: VSS, VDD3V3, VDD1V8, PA[14:0]
SCHEMATIC07 = schematic 07. SCHEMATIC, on sheet 00. System Block: VSS, SYSPWR_EN, VDD5V, VDD3V3, PN11, nRESET, PN14
SCHEMATIC03 = schematic 03. SCHEMATIC, on sheet 00. System Block: VSS, PG[15:11], PG0, nRESET, PG[7:2], PD[11:6], PE[15:14], VDD3V3, PA[14:0]
SCHEMATIC01 = schematic 01. SCHEMATIC, on sheet 00. System Block: VSS, SYSPWR_EN, VDD5V, VDD3V3, VDD1V8, VDD1V2, USBD_USB5V, N123_USB5V, VDD2V5, DRAM_VDD
SCHEMATIC08 = schematic 08. SCHEMATIC, on sheet 00. System Block: VSS, nRESET, VDD3V3, VDD1V8
SCHEMATIC10 = schematic 10. SCHEMATIC, on sheet 00. System Block: PN[5:4], PG[15:11], VSS, PC[3:2], VDD3V3
SCHEMATIC04 = schematic 04. SCHEMATIC, on sheet 00. System Block: VSS, PN[1:0], PC12, VDD3V3, VDD2V5, DRAM_VDD, VDD1V2
SCHEMATIC09 = schematic 09. SCHEMATIC, on sheet 00. System Block: VSS, nRESET, VDD3V3
SCHEMATIC02 = schematic 02. SCHEMATIC, on sheet 00. System Block: VSS, PL[13:12], PF15, HSUSB0_ID, nRESET, PC[7:0], PL[15:14], PN[1:0], PN[5:4], PB[15:8], VDD3V3, VDD1V2, PN11, PN[15:14]
SCHEMATIC05 = schematic 05. SCHEMATIC, on sheet 00. System Block: VSS, PG0, PG[7:2], PD[11:6], PC[1:0], PC[5:4], PL[15:14], PN15, PB[15:8], nRESET, PC12, VDD5V, VDD3V3, PC6, PC7

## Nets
5VIN: C207.1 C208.2 D2.2 D5.2 D6.2 D7.2 R213.2 R214.2 R215.1 R216.1 U23.1(Vin)
AVDD_3V3: C80.2 C81.2 C82.1 L16.1 U1.203(AVDD_EADC0) U1.208(AVDD_ADC0)
AVSS: C80.1 C81.1 C82.2 R35.1 U1.209(AVSS)
GND_EARTH: C138.1 C139.1 C142.1 C143.1 C144.1 C146.2 C159.2 C160.1 C161.1 C162.1 C163.1 C166.1 CON6.13(Shield) CON6.14(Shield) CON7.13(Shield) CON7.14(Shield) ; also on sheet 11
SCHEMATIC01/VDDIO10_VDD3V3: C227.2 C228.1 L39.1 U1.171(VDDIO10)
SCHEMATIC02/VDDIO0_VDD3V3: C72.2 C73.1 L13.1 U1.215(VDDIO0)
SCHEMATIC02/VDDIO6_VDD3V3: C76.2 C77.1 L14.1 U1.148(VDDIO6)
SCHEMATIC02/VDDIO7_VDD3V3: C78.2 C79.1 L15.1 U1.158(VDDIO7)
SCHEMATIC12/VDD_HSUSB0: C195.1 C196.1 L34.1 U1.22(VDD_HSUSB0)
SCHEMATIC12/VDD_HSUSB1: C197.1 C198.1 C199.1 L35.1 U1.14(VDD_HSUSB1) U1.18(VDD_HSUSB1)
VDD1V2: C74.2 C209.1 C210.1 R203.1 R204.1 R205.1 ; also on sheet 10
VDD1V8: C213.1 C214.1 L26.1 R207.1 ; also on sheet 12
VDD2V5: C215.1 C216.1 R208.1 ; also on sheet 10
VDD3V3: C211.1 C212.1 L13.2 L14.2 L15.2 L16.2 L27.1 L29.1 L30.1 L32.1 L34.2 L35.2 L39.2 R24.1 R25.1 R26.1 R27.1 R30.1 R31.1 R32.1 R33.1 R133.1 R166.2 R167.2 R173.2 R206.1 R212.1 ; also on sheet 9 10 11 12 13
VDD5V: C17.1 C20.1 C39.1 C54.1 C57.1 C64.1 C66.1 C200.2 C203.2 R1.2 R215.2 R216.2 U2.3(VIN) U3.4(Vin) U4.4(Vin) U5.4(Vin) U6.4(Vin) U21.2(IN) U21.3(IN) U22.2(IN) U22.3(IN) U23.8(Vout) U24.3(IN) ; also on sheet 11 13
VSS: C17.2 C20.2 C36.2 C37.2 C38.2 C39.2 C51.2 C53.2 C54.2 C55.2 C56.2 C57.2 C59.2 C60.2 C63.2 C64.2 C65.2 C66.2 C67.2 C68.2 C69.2 C70.2 C71.2 C72.1 C73.2 C75.1 C76.1 C77.2 C78.1 C79.2 C113.2 C114.2 C115.2 C120.1 C123.1 C124.2 C125.2 C126.2 C127.2 C128.2 C129.2 C130.2 C131.2 C132.2 C133.2 C134.2 C135.2 C136.2 C137.2 C138.2 C139.2 C140.2 C141.2 C142.2 C143.2 C144.2 C145.1 C147.2 C148.2 C149.2 C150.2 C151.2 C152.2 C153.2 C154.2 C155.1 C156.2 C157.2 C158.2 C160.2 C161.2 C162.2 C163.2 C164.2 C165.1 C166.2 C168.2 C172.1 C178.2 C179.2 C180.2 C185.2 C186.2 C187.2 C188.2 C189.2 C190.2 C191.2 C192.2 C193.2 C194.1 C195.2 C196.2 C197.2 C198.2 C199.2 C200.1 C201.1 C202.2 C203.1 C204.1 C205.1 C206.2 C207.2 C208.1 C209.2 C210.2 C211.2 C212.2 C213.2 C214.2 C215.2 C216.2 C217.2 C218.2 C227.1 C228.2 C229.2 C231.2 C232.2 C233.2 C234.2 CB7.2 CB8.1 CON2.2 CON2.3 D7.1 J1.2 J9.5 J10.2 L31.1 L33.1 L36.1 L37.1 LED1.2(CATHODE) LED3.2(CATHODE) Q1.2(E) Q7.2(E) Q8.3(C) R6.1 R12.1 R13.1 R21.1 R22.2 R29.2 R35.2 R77.2 R79.2 R81.2 R85.2 R86.2 R88.2 R89.2 R96.1 R103.1 R112.2 R115.2 R116.2 R122.1 R128.2 R132.2 R136.2 R138.2 R154.1 R171.1 R175.1 R189.2 R213.1 R217.2 R218.2 R254.1 SW1.2 SW2.2 SW3.2 SW4.2 SW5.2 SW6.2 U2.4(PGND) U2.8(AGND) U2.9(EPAD) U3.2(GND) U4.2(GND) U5.2(GND) U6.2(GND) U14.41(E_PAD) U16.33(E_PAD) U18.12(VSSD) U18.18(MODE) U19.8(VSS) U19.32(PVSS) U19.33(VSS) U20.2(Vn) U21.1(GND) U22.1(GND) U23.2(GND) U23.9(GND) U24.1(GND) X2.2(GND) X2.4(GND) X3.2(GND) X3.4(GND) X4.2(GND) X4.4(GND) X5.2(GND) X5.4(GND) ; also on sheet 9 10 11 12 13
VSSA: C167.1 C169.2 C170.2 C171.1 C173.2 C174.2 C177.2 C184.2 L31.2 Q4.2(SOURCE) Q5.2(SOURCE) R136.1 R138.1 R142.1 R150.2 R153.1 R155.2 U18.24(VSSSPK) U18.28(VSSA) U18.33(EPAD)
AUDIO_3V3: C167.2 C169.1 L30.2 R134.2 R135.1 U18.31(VDDA)
AUDIO_D3V3: C168.1 C180.1 R133.2 R140.2 R141.2 R148.2 R152.2 U18.13(VDDC) U18.14(VDDB)
DRAM_VDD: C217.1 C218.1 R209.1 ; also on sheet 10
E_DVDDRG: C126.1 C128.1 R78.1 R80.1 R82.1 R83.1 R109.1 U14.28(DVDD_RG)
E_VDD3V3: C115.1 C123.2 C129.1 C133.1 C145.2 L27.2 R91.1 R97.1 R99.1 R108.1 U14.11(AVDD33) U14.29(DVDD33) U14.40(AVDD33)
E_VDDIO: C113.1 C114.1 L26.2 U1.179(VDDIO8)
F_PHY_VDD3V3: C165.2 R111.1 R114.1 R117.2 R118.2 R119.1 R123.1 R130.2 R131.2 U16.14(DVDD33)
F_VDD3V3: C147.1 C148.1 L29.2 R110.2 R111.2 U1.191(VDDIO9)
HSUSB0_ID: J10.1 R167.1 R169.2 R219.2 U1.2(HSUSB0_ID)
N123_USB5V: C188.1 C193.1 CON9.1(V+) D5.1 U19.9(VBUS) U20.5(Vp)
nRESET: C75.2 Q1.3(C) R24.2 R108.2 R118.1 SW2.3 U1.1(nRESET/WDT_nRST) U14.12(PHYRSTB) U16.21(PHYRSTB) ; also on sheet 9 11 13
PB8: U1.204(PB8/EPWM2_BRAKE0/UART2_nCTS/UART1_RXD/I2C2_SDA/SPI0_SS1/SPI0_I2SMCLK/ADC0_CH0(A0)/EBI_nCS0/TM4/QEI2_INDEX/KPI_ROW6) ; also on sheet 11
PB9: U1.205(PB9/EPWM2_CH4/UART2_nRTS/UART1_TXD/I2C2_SCL/SPI0_CLK/I2S0_MCLK/CCAP1_HSYNC/ADC0_CH1(A1)/EBI_ALE/EBI_AD13/TM0_EXT/I2S1_MCLK/SC0_nCD/QEI2_A/KPI_ROW7) ; also on sheet 11
PB10: U1.206(PB10/EPWM2_CH5/UART2_RXD/CAN0_RXD/SPI0_MOSI/EBI_MCLK/CCAP1_VSYNC/ADC0_CH2(A2)/EBI_ADR15/EBI_AD14/TM5/I2C1_SDA/INT1/QEI2_B) ; also on sheet 11
PB11: U1.207(PB11/EPWM2_BRAKE1/UART2_TXD/CAN0_TXD/SPI0_MISO/I2S1_MCLK/CCAP1_SFIELD/ADC0_CH3(VSENSE)/EBI_nCS2/EBI_ALE/TM5_EXT/I2C1_SCL/INT2/QEI2_INDEX) ; also on sheet 11
PB12: U1.211(PB12/EPWM2_CH0/UART4_nCTS/UART3_RXD/I2C3_SDA/CAN2_RXD/I2S1_LRCK/ADC0_CH4(YM)/EBI_ADR16/ECAP2_IC0) ; also on sheet 11
PB13: U1.212(PB13/EPWM2_CH1/UART4_nRTS/UART3_TXD/I2C3_SCL/CAN2_TXD/I2S1_BCLK/ADC0_CH5(YP)/EBI_ADR17/ECAP2_IC1) ; also on sheet 11
PB14: U1.213(PB14/EPWM2_CH2/UART4_RXD/CAN1_RXD/I2C4_SDA/I2S1_DI/ADC0_CH6(XM)/EBI_ADR18/ECAP2_IC2) ; also on sheet 11
PB15: U1.214(PB15/EPWM2_CH3/UART4_TXD/CAN1_TXD/I2C4_SCL/I2S1_DO/ADC0_CH7(XP)/EBI_ADR19) ; also on sheet 11
PC0: U1.142(PC0/I2C4_SDA/SD0_CMD/eMMC0_CMD) ; also on sheet 11
PC1: U1.143(PC1/I2C4_SCL/SD0_CLK/eMMC0_CLK) ; also on sheet 11
PC2: Q4.1(GATE) Q5.1(GATE) R152.1 R154.2 U1.144(PC2/CAN0_RXD/SD0_DAT0/eMMC0_DAT0)
PC3: CON8.5(DETECT) R148.1 U1.145(PC3/CAN0_TXD/SD0_DAT1/eMMC0_DAT1) U18.3(LLIN/GPIO2)
PC4: U1.146(PC4/I2C5_SDA/SD0_DAT2/eMMC0_DAT2) ; also on sheet 11
PC5: U1.147(PC5/I2C5_SCL/SD0_DAT3/eMMC0_DAT3) ; also on sheet 11
PC6: U1.149(PC6/CAN1_RXD/SD0_nCD) ; also on sheet 11
PC7: U1.150(PC7/CAN1_TXD/SD0_WP) ; also on sheet 11
PE14: J8.1 R158.2 ; also on sheet 9
PE15: J8.2 R159.2 ; also on sheet 9
PF15: R168.1 R171.2 U1.3(PF15/HSUSB0_VBUSVLD)
PG11: R145.2 ; also on sheet 9
PG12: R146.2 ; also on sheet 9
PG13: R147.2 ; also on sheet 9
PG14: R149.2 ; also on sheet 9
PG15: R151.2 ; also on sheet 9
PL12: R172.2 R175.2 U1.4(PL12/EPWM0_SYNC_IN/UART7_nCTS/ECAP1_IC0/UART14_RXD/SPI0_SS0/I2S1_LRCK/SC1_CLK/EBI_AD0/HSUSBH_PWREN/I2C2_SDA/TM0/EPWM0_CH2/EBI_AD11/RGMII0_PPS/RMII0_PPS) U22.4(EN)
PL13: R173.1 U1.5(PL13/EPWM0_SYNC_OUT/UART7_nRTS/ECAP1_IC1/UART14_TXD/SPI0_CLK/I2S1_BCLK/SC1_DAT/EBI_AD1/HSUSBH_OVC/I2C2_SCL/TM0_EXT/EPWM0_CH3/EBI_AD12/RGMII1_PPS/RMII1_PPS) U21.5(OC#) U22.5(OC#)
PL14: U1.6(PL14/EPWM0_CH2/UART7_RXD/CAN1_RXD/SPI0_MOSI/I2S1_DI/SC1_RST/EBI_AD2/TM2/INT0/EBI_AD13) ; also on sheet 11
PL15: U1.7(PL15/EPWM0_CH1/UART7_TXD/TRACE_CLK/CAN1_TXD/SPI0_MISO/I2S1_DO/SC1_RWR/EBI_AD3/TM2_EXT/INT2/EBI_AD14) ; also on sheet 11
PN0: U1.152(PN0/I2C2_SDA/CCAP1_DATA0) ; also on sheet 10
PN1: U1.153(PN1/I2C2_SCL/CCAP1_DATA1) ; also on sheet 10
PN4: R140.1 R143.2 U1.156(PN4/I2C1_SDA/CCAP1_DATA4)
PN5: R141.1 R144.2 U1.157(PN5/I2C1_SCL/CCAP1_DATA5)
PN11: U1.162(PN11/CAN2_TXD/CCAP1_PIXCLK) ; also on sheet 13
PN14: U1.165(PN14/UART6_RXD/CAN3_RXD/SPI1_SS1/CCAP1_SFIELD/SPI1_I2SMCLK) ; also on sheet 13
PN15: U1.166(PN15/EPWM2_CH4/UART6_TXD/CAN3_TXD/I2S0_MCLK/SPI1_SS1/SPI1_I2SMCLK/SC0_nCD/EADC0_ST/CLKO/TM6) ; also on sheet 11
RTC3V3: C229.1 D3.1 R210.1 U24.2(OUT) U24.4(OUT)
SCHEMATIC01/N1: CON2.1 D2.1
SCHEMATIC01/N2: LED2.2(CATHODE) U23.4(#Fault)
SCHEMATIC01/N3: LED2.1(ANODE) R214.1
SCHEMATIC01/N4: R218.1 U23.7(Ilimit)
SCHEMATIC01/N5: R217.1 U23.5(#En) U23.6(Bat)
SCHEMATIC01/N6: LED1.1(ANODE) R1.1
SCHEMATIC01/N7: C38.1 R4.2 U2.7(EN)
SCHEMATIC01/N8: L4.1 U2.6(LX)
SCHEMATIC01/N9: C35.2 R5.2 R6.2 U2.1(FB)
SCHEMATIC01/N10: C35.1 C36.1 C37.1 L4.2 R5.1 R203.2 R204.2 R205.2
SCHEMATIC01/N11: C53.1 R7.2 U3.1(EN)
SCHEMATIC01/N12: L7.1 U3.3(SW)
SCHEMATIC01/N13: C50.1 R10.1 R12.2 U3.5(FB)
SCHEMATIC01/N14: C50.2 C51.1 L7.2 R10.2 R206.2
SCHEMATIC01/N15: LED3.1(ANODE) R212.2
SCHEMATIC01/N16: C56.1 R8.2 U4.1(EN)
SCHEMATIC01/N17: L8.1 U4.3(SW)
SCHEMATIC01/N18: C52.1 R11.1 R13.2 U4.5(FB)
SCHEMATIC01/N19: C52.2 C55.1 L8.2 R11.2 R207.2
SCHEMATIC01/N20: C63.1 R17.2 U5.1(EN)
SCHEMATIC01/N21: L11.1 U5.3(SW)
SCHEMATIC01/N22: C61.1 R19.1 R21.2 U5.5(FB)
SCHEMATIC01/N23: C59.1 C61.2 L11.2 R19.2 R208.2
SCHEMATIC01/N24: C65.1 R18.2 U6.1(EN)
SCHEMATIC01/N25: L12.1 U6.3(SW)
SCHEMATIC01/N26: C62.1 R20.1 R252.1 R253.2 U6.5(FB)
SCHEMATIC01/N27: C60.1 C62.2 L12.2 R20.2 R209.2
SCHEMATIC01/N28: R22.1 R252.2
SCHEMATIC01/N29: R253.1 R254.2
SCHEMATIC01/N30: C67.1 R251.2 U1.10(VBAT)
SCHEMATIC01/N31: D3.2 D4.2 R251.1
SCHEMATIC01/N32: D4.1 J1.1
SCHEMATIC01/RTC_nRWAKE: R189.1 SW1.3 U1.11(RTC_nRWAKE)
SCHEMATIC01/RTC_RPWR: R250.2 U1.9(RTC_RPWR)
SCHEMATIC01/X32_IN: C68.1 U1.12(X32_IN) X1.2
SCHEMATIC01/X32_OUT: C69.1 U1.13(X32_OUT) X1.1
SCHEMATIC01/XT1_IN: C70.1 R23.2 U1.169(XT1_IN) X2.1(XIN)
SCHEMATIC01/XT1_OUT: C71.1 R23.1 U1.170(XT1_OUT) X2.3(XOUT)
SCHEMATIC02/KEY0: R30.2 SW3.3 U1.154(PN2/CAN0_RXD/CCAP1_DATA2)
SCHEMATIC02/KEY1: R31.2 SW4.3 U1.155(PN3/CAN0_TXD/CCAP1_DATA3)
SCHEMATIC02/KEY2: R32.2 SW5.3 U1.163(PN12/UART6_nCTS/UART12_RXD/I2C5_SDA/CCAP1_HSYNC)
SCHEMATIC02/KEY3: R33.2 SW6.3 U1.164(PN13/UART6_nRTS/UART12_TXD/I2C5_SCL/CCAP1_VSYNC)
SCHEMATIC02/LED0: LEDR1.2 U1.159(PN6/CAN1_RXD/CCAP1_DATA6)
SCHEMATIC02/LED1: LEDG1.2 U1.160(PN7/CAN1_TXD/CCAP1_DATA7)
SCHEMATIC02/LED2: LEDY1.2 U1.161(PN10/CAN2_RXD/CCAP1_SCLK)
SCHEMATIC02/N33: C74.1 Q1.1(B) R29.1
SCHEMATIC02/N34: LEDR1.1 R25.2
SCHEMATIC02/N35: LEDG1.1 R26.2
SCHEMATIC02/N36: LEDY1.1 R27.2
SCHEMATIC08/E_AVDD10: C120.2 C130.1 C131.1 C136.1 C137.1 C140.1 L28.2 R100.1 U14.3(AVDD10) U14.8(AVDD10) U14.21(DVDD10) U14.38(AVDD10)
SCHEMATIC08/E_CLKOUT: T6.1 U14.35(CLKOUT)
SCHEMATIC08/E_DA+: CON6.1(DA+) U15.2(TD1+)
SCHEMATIC08/E_DA-: CON6.2(DA-) U15.3(TD1-)
SCHEMATIC08/E_DB+: CON6.3(DB+) U15.5(TD2+)
SCHEMATIC08/E_DB-: CON6.6(DB-) U15.6(TD2-)
SCHEMATIC08/E_DC+: CON6.4(DC+) U15.8(TD3+)
SCHEMATIC08/E_DC-: CON6.5(DC-) U15.9(TD3-)
SCHEMATIC08/E_DD+: CON6.7(DD+) U15.11(TD4+)
SCHEMATIC08/E_DD-: CON6.8(DD-) U15.12(TD4-)
SCHEMATIC08/E_ETH_XI: C124.1 R98.2 U14.36(XTAL_IN) X3.1(XIN)
SCHEMATIC08/E_ETH_XO: C125.1 R98.1 U14.37(XTAL_OUT/EXT_CLK) X3.3(XOUT)
SCHEMATIC08/E_INTB: R97.2 U14.31(INTB/PMEB)
SCHEMATIC08/E_LED0: R88.1 U14.32(LED0/CFG_EXT)
SCHEMATIC08/E_LED1: C135.1 R89.1 R102.1 U14.33(LED1/CFG_LDO0)
SCHEMATIC08/E_LED2: C134.1 R91.2 R101.1 U14.34(LED2/CFG_LDO1)
SCHEMATIC08/E_MDIN0: U14.2(MDIN0) U15.22(MX1-)
SCHEMATIC08/E_MDIN1: U14.5(MDIN1) U15.19(MX2-)
SCHEMATIC08/E_MDIN2: U14.7(MDIN2) U15.16(MX3-)
SCHEMATIC08/E_MDIN3: U14.10(MDIN3) U15.13(MX4-)
SCHEMATIC08/E_MDIP0: U14.1(MDIP0) U15.23(MX1+)
SCHEMATIC08/E_MDIP1: U14.4(MDIP1) U15.20(MX2+)
SCHEMATIC08/E_MDIP2: U14.6(MDIP2) U15.17(MX3+)
SCHEMATIC08/E_MDIP3: U14.9(MDIP3) U15.14(MX4+)
SCHEMATIC08/E_REG_OUT: C127.1 L28.1 R100.2 U14.30(REG_OUT)
SCHEMATIC08/N66: CON6.10(LED+) R99.2
SCHEMATIC08/N67: CON6.9(LED-) R101.2
SCHEMATIC08/N68: CON6.12(LED+) R102.2
SCHEMATIC08/N69: CON6.11(LED-) R103.2
SCHEMATIC08/N70: R104.2 U15.1(TCT1)
SCHEMATIC08/N71: R105.2 U15.4(TCT2)
SCHEMATIC08/N72: R106.2 U15.7(TCT3)
SCHEMATIC08/N73: R107.2 U15.10(TCT4)
SCHEMATIC08/N80: C146.1 R104.1 R105.1 R106.1 R107.1
SCHEMATIC08/N81: C141.1 U15.15(MCT4) U15.18(MCT3) U15.21(MCT2) U15.24(MCT1)
SCHEMATIC08/PE0: U1.175(PE0/UART9_nCTS/UART8_RXD/CCAP1_DATA0/RGMII0_MDC/RMII0_MDC) U14.13(MDC)
SCHEMATIC08/PE1: R109.2 U1.176(PE1/UART9_nRTS/UART8_TXD/CCAP1_DATA1/RGMII0_MDIO/RMII0_MDIO) U14.14(MDIO)
SCHEMATIC08/PE2: U1.177(PE2/UART9_RXD/CCAP1_DATA2/RGMII0_TXCTL/RMII0_TXEN) U14.19(TXCTL)
SCHEMATIC08/PE3: U1.178(PE3/UART9_TXD/CCAP1_DATA3/RGMII0_TXD0/RMII0_TXD0) U14.18(TXD0)
SCHEMATIC08/PE4: U1.181(PE4/UART4_nCTS/UART3_RXD/CCAP1_DATA4/RGMII0_TXD1/RMII0_TXD1) U14.17(TXD1)
SCHEMATIC08/PE5: C132.1 R85.1 U1.182(PE5/UART4_nRTS/UART3_TXD/CCAP1_DATA5/RGMII0_RXCLK/RMII0_REFCLK) U14.27(RXC/PHYAD1)
SCHEMATIC08/PE6: R86.1 U1.183(PE6/UART4_RXD/CCAP1_DATA6/RGMII0_RXCTL/RMII0_CRSDV) U14.26(RXCTL/PHYAD2)
SCHEMATIC08/PE7: R79.1 R80.2 U1.184(PE7/UART4_TXD/CCAP1_DATA7/RGMII0_RXD0/RMII0_RXD0) U14.25(RXD0/RXDLY)
SCHEMATIC08/PE8: R81.1 R82.2 U1.185(PE8/UART13_nCTS/UART12_RXD/CCAP1_SCLK/RGMII0_RXD1/RMII0_RXD1) U14.24(RXD1/TXDLY)
SCHEMATIC08/PE9: R77.1 R78.2 U1.186(PE9/UART13_nRTS/UART12_TXD/CCAP1_PIXCLK/RGMII0_RXD2/RMII0_RXERR) U14.23(RXD2/PLLOFF)
SCHEMATIC08/PE10: R83.2 U1.187(PE10/UART15_nCTS/UART14_RXD/SPI1_SS0/CCAP1_HSYNC/RGMII0_RXD3) U14.22(RXD3/PHYAD0)
SCHEMATIC08/PE11: U1.188(PE11/UART15_nRTS/UART14_TXD/SPI1_CLK/CCAP1_VSYNC/RGMII0_TXCLK) U14.20(TXC)
SCHEMATIC08/PE12: U1.189(PE12/UART15_RXD/SPI1_MOSI/CCAP1_DATA8/RGMII0_TXD2) U14.16(TXD2)
SCHEMATIC08/PE13: U1.190(PE13/UART15_TXD/SPI1_MISO/CCAP1_DATA9/RGMII0_TXD3) U14.15(TXD3)
SCHEMATIC09/F_AVDD10: C153.1 U16.2(AVDD10OUT)
SCHEMATIC09/F_DVDD10: C149.1 U16.29(DVDD10OUT)
SCHEMATIC09/F_ETH_XI: C151.1 R113.2 U16.31(CKXTAL1) X4.1(XIN)
SCHEMATIC09/F_ETH_XO: C152.1 R113.1 U16.32(CKXTAL2) X4.3(XOUT)
SCHEMATIC09/F_LED0: C156.1 R114.2 R120.1 U16.24(LED0/PHYAD[0]/PMEB)
SCHEMATIC09/F_LED1: C154.1 R115.1 R121.1 U16.25(LED1/PHYAD[1])
SCHEMATIC09/F_MDI0+: U16.3(MDI+[0]) U17.8(TD+)
SCHEMATIC09/F_MDI0-: U16.4(MDI-[0]) U17.6(TD-)
SCHEMATIC09/F_MDI1+: U16.5(MDI+[1]) U17.3(RD+)
SCHEMATIC09/F_MDI1-: U16.6(MDI-[1]) U17.1(RD-)
SCHEMATIC09/F_PHY_AVDD3V3: C150.1 C155.2 R110.1 U16.7(AVDD33) U16.30(AVDD33)
SCHEMATIC09/F_RX+: CON7.3(DB+) U17.14(RX+)
SCHEMATIC09/F_RX-: CON7.6(DB-) U17.16(RX-)
SCHEMATIC09/F_TX+: CON7.1(DA+) U17.9(TX+)
SCHEMATIC09/F_TX-: CON7.2(DA-) U17.11(TX-)
SCHEMATIC09/N82: CON7.10(LED+) R119.2
SCHEMATIC09/N83: CON7.9(LED-) R120.2
SCHEMATIC09/N84: CON7.12(LED+) R121.2
SCHEMATIC09/N85: CON7.11(LED-) R122.2
SCHEMATIC09/N86: CON7.7(DD+) CON7.8(DD-) R124.2
SCHEMATIC09/N87: CON7.4(DC+) CON7.5(DC-) R125.2
SCHEMATIC09/N88: R126.2 U17.15(CT)
SCHEMATIC09/N89: R127.2 U17.10(CT)
SCHEMATIC09/N91: C159.1 R124.1 R125.1 R126.1 R127.1
SCHEMATIC09/N92: C157.1 U17.2(CT)
SCHEMATIC09/N93: C158.1 U17.7(CT)
SCHEMATIC09/N94: R116.1 U16.1(RSET)
SCHEMATIC09/N95: R123.2 U16.8(RXDV)
SCHEMATIC09/PF0: U1.192(PF0/UART2_nCTS/UART1_RXD/RGMII0_RXD3/RGMII1_MDC/RMII1_MDC/KPI_COL0) U16.22(MDC)
SCHEMATIC09/PF1: R117.1 U1.193(PF1/UART2_nRTS/UART1_TXD/RGMII0_TXCLK/RGMII1_MDIO/RMII1_MDIO/KPI_COL1) U16.23(MDIO)
SCHEMATIC09/PF2: U1.194(PF2/UART2_RXD/RGMII0_TXD2/RGMII1_TXCTL/RMII1_TXEN/KPI_COL2) U16.20(TXEN)
SCHEMATIC09/PF3: U1.195(PF3/UART2_TXD/RGMII0_TXD3/RGMII1_TXD0/RMII1_TXD0/KPI_COL3) U16.16(TXD[0])
SCHEMATIC09/PF4: U1.196(PF4/UART11_nCTS/UART10_RXD/I2S0_LRCK/SPI1_SS0/RGMII1_TXD1/RMII1_TXD1/CAN2_RXD/KPI_ROW0) U16.17(TXD[1])
SCHEMATIC09/PF5: C164.1 R129.1 U1.197(PF5/UART11_nRTS/UART10_TXD/I2S0_BCLK/SPI1_CLK/RGMII1_RXCLK/RMII1_REFCLK/CAN2_TXD/KPI_ROW1)
SCHEMATIC09/PF6: U1.198(PF6/UART11_RXD/I2S0_DI/SPI1_MOSI/RGMII1_RXCTL/RMII1_CRSDV/I2C4_SDA/SC0_CLK/KPI_ROW2) U16.26(CRS/CRS_DV)
SCHEMATIC09/PF7: U1.199(PF7/UART11_TXD/I2S0_DO/SPI1_MISO/RGMII1_RXD0/RMII1_RXD0/I2C4_SCL/SC0_DAT/KPI_ROW3) U16.9(RXD[0])
SCHEMATIC09/PF8: R128.1 U1.200(PF8/UART13_RXD/I2C5_SDA/SPI0_SS0/RGMII1_RXD1/RMII1_RXD1/SC0_RST/KPI_COL4) U16.10(RXD[1])
SCHEMATIC09/PF9: R112.1 U1.201(PF9/UART13_TXD/I2C5_SCL/SPI0_SS1/RGMII1_RXD2/RMII1_RXERR/SC0_PWR/KPI_COL5) U16.28(RXER/FXEN)
SCHEMATIC09/RXD2/INTB: R130.1 U16.11(RXD[2]/INTB)
SCHEMATIC09/RXD3: R131.1 R132.1 U16.12(RXD[3]/CLK_CTL)
SCHEMATIC09/TXC: R129.2 U16.15(TXC)
SCHEMATIC10/I2S0_BCLK: R147.1 U18.8(BCLK)
SCHEMATIC10/I2S0_DI: R149.1 U18.9(ADCOUT)
SCHEMATIC10/I2S0_DO: R151.1 U18.10(DACIN)
SCHEMATIC10/I2S0_LRCK: R146.1 U18.7(FS)
SCHEMATIC10/I2S0_MCLK: R145.1 U18.11(MCLK)
SCHEMATIC10/LHP: C181.1 Q4.3(DRAIN) U18.30(LHP)
SCHEMATIC10/LMICN: C176.2 U18.2(LMICN)
SCHEMATIC10/LMICP: C175.2 U18.1(LMICP)
SCHEMATIC10/LSPKOUT: J7.2 U18.25(LSP_O)
SCHEMATIC10/MIC_BIAS: C173.1 C174.1 R135.2 R137.2 R139.2 R156.1
SCHEMATIC10/N96: R137.1 U18.32(MICBIAS)
SCHEMATIC10/N97: C181.2 CON8.1(LEFT) R150.1
SCHEMATIC10/N98: C182.2 CON8.2(RIGHT) R153.2
SCHEMATIC10/N101: C183.1 C184.1 CON8.4(M/G) R156.2
SCHEMATIC10/N102: CON8.3(G/M) CON8.6(GND) CON8.7(MS) R155.1
SCHEMATIC10/N117: C175.1 M1.P(1) R139.1
SCHEMATIC10/N118: C176.1 M1.N(2) R142.2
SCHEMATIC10/RHP: C182.1 Q5.3(DRAIN) U18.29(RHP)
SCHEMATIC10/RMICN: C177.1 U18.5(RMICN)
SCHEMATIC10/RMICP: C183.2 U18.4(RMICP)
SCHEMATIC10/RSPKOUT: J7.1 U18.23(RSP_O)
SCHEMATIC10/SCL: C178.1 R144.1 U18.16(SCLK)
SCHEMATIC10/SDA: C179.1 R143.1 U18.17(SDIO)
SCHEMATIC10/VREF: C172.2 U18.27(VREF)
SCHEMATIC11/N99: C194.2 CON9.6(\) CON9.7(\) CON9.8(\) CON9.9(\)
SCHEMATIC11/N100: CON9.5(GND) L33.2
SCHEMATIC11/N123_12M_I: C191.1 U19.30(XT_IN) X5.1(XIN)
SCHEMATIC11/N123_12M_O: C192.1 U19.29(XT_OUT) X5.3(XOUT)
SCHEMATIC11/N123_D+: R161.2 U19.12(D+)
SCHEMATIC11/N123_D-: R160.2 U19.11(D-)
SCHEMATIC11/N123_ICE_CLK: J9.3 U19.24(ICE_CLK)
SCHEMATIC11/N123_ICE_DAT: J9.2 U19.23(ICE_DAT)
SCHEMATIC11/N123_LDO: C189.1 U19.6(LDO_OUT)
SCHEMATIC11/N123_nRST: C187.1 J9.4 R157.1 U19.31(RESET#)
SCHEMATIC11/N123_USB_LDO: C186.1 U19.10(USB_LDO_OUT)
SCHEMATIC11/UR0_RX: R159.1 U19.5(TX1/PB.5)
SCHEMATIC11/UR0_TX: R158.1 U19.4(RX1/PB.4)
SCHEMATIC11/VCOM_D+: CON9.3(D+) R161.1 U20.6(CH4)
SCHEMATIC11/VCOM_D-: CON9.2(D-) R160.1 U20.4(CH3)
SCHEMATIC12/HSUSB0_D+: C232.1 R165.2 U1.20(HSUSB0_D+)
SCHEMATIC12/HSUSB0_D-: C231.1 R164.2 U1.19(HSUSB0_D-)
SCHEMATIC12/HSUSB0_VBUS: C201.2 CB8.2 CON10.1(V+) Q6.2(S) U21.6(OUT) U21.7(OUT) U21.8(OUT)
SCHEMATIC12/HSUSB1_D+: C234.1 R176.2 U1.16(HSUSB1_D+)
SCHEMATIC12/HSUSB1_D-: C233.1 R174.2 U1.15(HSUSB1_D-)
SCHEMATIC12/HSUSB1_VBUS: C204.2 C205.2 CON11.1(VBUS) U22.6(OUT) U22.7(OUT) U22.8(OUT)
SCHEMATIC12/N103: Q7.1(B) R169.1
SCHEMATIC12/N104: Q8.1(B) R172.1
SCHEMATIC12/N105: Q7.3(C) Q8.2(E) R166.1 R170.2 U21.4(EN)
SCHEMATIC12/N106: C202.1 CON10.6(\) CON10.7(\) CON10.8(\) CON10.9(\)
SCHEMATIC12/N107: CON10.2(D-) R164.1
SCHEMATIC12/N108: CON10.3(D+) R165.1
SCHEMATIC12/N111: CON10.4(ID) R219.1
SCHEMATIC12/N112: CON10.5(GND) L36.2
SCHEMATIC12/N113: CON11.2(D-) R174.1
SCHEMATIC12/N114: CON11.3(D+) R176.1
SCHEMATIC12/N115: CON11.4(GND) L37.2
SCHEMATIC12/N116: C206.1 CON11.5(Shield) CON11.6(Shield)
SCHEMATIC12/N119: Q6.1(G) R170.1
SPK_3V3: C170.1 C171.2 R134.1 U18.26(VDDSPK)
SYSPWR_EN: R4.1 R7.1 R8.1 R17.1 R18.1 R210.2 R250.1 ; also on sheet 13
USBD_USB5V: D6.1 Q6.3(D) R168.2
VCOM_3V3: C185.1 C190.1 CB7.1 J9.1 L32.2 R157.2 T5.1 U19.7(LDO_IN_5V) U19.25(AVDD)
SCHEMATIC08/N07628: R96.2 U14.39(RSET)

Not connected (* = marked no-connect by the designer): CON9 4(ID)*; SW1 1* 4*; SW2 1* 4*; SW3 1* 4*; SW4 1* 4*; SW5 1* 4*; SW6 1* 4*; U1 167(PK12/EPWM2_CH0/UART1_nCTS/UART13_RXD/I2C4_SDA/I2S0_LRCK/SPI1_SS0/SC0_CLK/TM10/INT2)*; U2 2(POK)* 5(NC)*; U16 13(RXC) 18(TXD[2]) 19(TXD[3]) 27(COL); U17 4(NC)* 5(NC)* 12(NC)* 13(NC)*; U18 6(RLIN/GPIO3)* 15(CSB/GPIO1)* 19(LAUXIN)* 20(RAUXIN)* 21(AUXOUT1)* 22(AUXOUT2)*; U19 1(INT0/PB.14)* 2(I2C1_SCL/PA.11)* 3(I2C1_SDA/PA.10)* 13(MOSI0_0/PC.3)* 14(MISO0_0/PC.2)* 15(SPI0_CLK/PC.1)* 16(SPI0_CS0/PC.0)* 17(MOSI1_1/PC.13)* 18(MISO1_1/PC.12)* 19(MOSI1_0/PC.11)* 20(MISO1_0/PC.10)* 21(SPI1_CLK/PC.9)* 22(SPI1_CS0/PC.8)* 26(SPI2_CLK/PD.1)* 27(MISO2_0/PD.2)* 28(MOSI2_0/PD.3)*; U20 1(CH1)* 3(CH2)*; U23 3(N.C.)*

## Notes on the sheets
sheet 2
- Pull-up to disable PLL@ALDPS mode
- RXC
- TXC
- Pull-up for add 2ns delay to TXC/RXC for data latch
- Note: The VDDIO8 is the input voltage of I/O
  group 8 and its voltage is 1.8V ~ 3.3V.
  This voltage should be matched with the
  voltage of external connected device. (The
  default is 1.8V on this board)
- PHY Address 1 :3'b001
- Internal 1.8V(E_LED0,1,2=0,0,1)
- RTL8211FDI
- RTL8211FI
sheet 3
- Note: The VDDIO9 is the input voltage of I/O
  group 9 and its voltage is 1.8V ~ 3.3V. This
  voltage should be matched with the voltage
  of external connected device. (The default
  is 3.3V on this board)
- PHY Address 1 :2'b01
sheet 4
- Codec
- Speaker
- Microphone
- (EPAD = VSSA)
- PG11~15 Connect to I2S0(SWJ)
- 3, Drain
- SI2302 (NMOS)
- Earphone
- 1, Gate
- 2, Source
- 3
- MS
- 1
- 4
- 2
- 6
- 5
- CTIA
- L
- R
- GND
- MIC
sheet 5
- NUC123 VCOM
- Note: The GPIO PE15 (UART0_RXD) pin must be
  pulled to high level through an external resistor or
  an internal pull-up resistor in the external device
  (such as a transceiver or MCU).
- VDDIO1 (VDD3V3)
- 10K
- PE15
- 1
sheet 6
- 3, Drain
- 3
  Collector
- SI2301 (PMOS)
- 2N3904 (NPN)
- USB0 Device/HOST
- 1
  Base
- 2
  Emitter
- 1, Gate
- 2, Source
- V2.3
- Short:USB0 HOST
- 3
  Collector
- S8550 (PNP)
- 1
  Base
- 2
  Emitter
- USB1 HOST
- V2.3
sheet 7
- 5V IN
- 5V
- 1.20V
- R
- G
- P_Fault
- P_Good
- RTC
- V2.3
- V2.3
- 3.3V
- 1.8V
- V2.3
- V2.3
- 24MHz Crystal
- 32768Hz Crystal
- 2.5V
- V2.3
- V2.3
- Option for the supply voltage of
  SDRAM power  (DRAM_VDD)
- 1. Mount R252 only, DRAM_VDD = 1.35V  (for
  MA35D16F887C/MA35D16F987C, DDR3L)
- 2. Mount R253 only, DRAM_VDD = 1.8V
  (for MA35D16F787C, DDR2)
sheet 8
- Reset
- Note: The VDDIO0 is the input
  voltage of I/O group 0 and its
  voltage is 3.3V only.
- 3
  Collector
- Note: The VDDIO6 is the input
  voltage of I/O group 6 and its
  voltage is 3.3V only.
- 2N3904 (NPN)
- 1
  Base
- 2
  Emitter
- KEY_0
- KEY_1
- KEY_2
- KEY_3
- Note: The VDDIO7 is the input voltage of I/O
  group 7 and its voltage is 1.8V ~ 3.3V. This
  voltage should be matched with the voltage of
  external connected device. (The default is
  3.3V on this board)
- LED_0
- LED_1
- LED_2
- R
- G
- Y
- Note: The AVDD_EADC0 and AVDD_ADC0 are the input
  voltages of EADC0 and ADC0 (includes the I/O votlage
  of PB8~PB15), their input voltages are 3.3V only.
